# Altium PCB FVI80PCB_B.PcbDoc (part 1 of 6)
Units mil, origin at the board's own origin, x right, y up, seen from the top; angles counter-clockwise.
Board outline 3540 x 3115 mil, 12 copper layers (Top Layer, Int1(GND), Int2(Signal), Int3(GND), Int4(Signal), Int5 (GND&PW), Int6 (GND&PW), Int7(Signal), Int8(GND), Int9(Signal), Int10(GND), Bottom Layer), stack 77.136 mil thick; 488 components, 321 nets, 1809 pads, 882 vias.
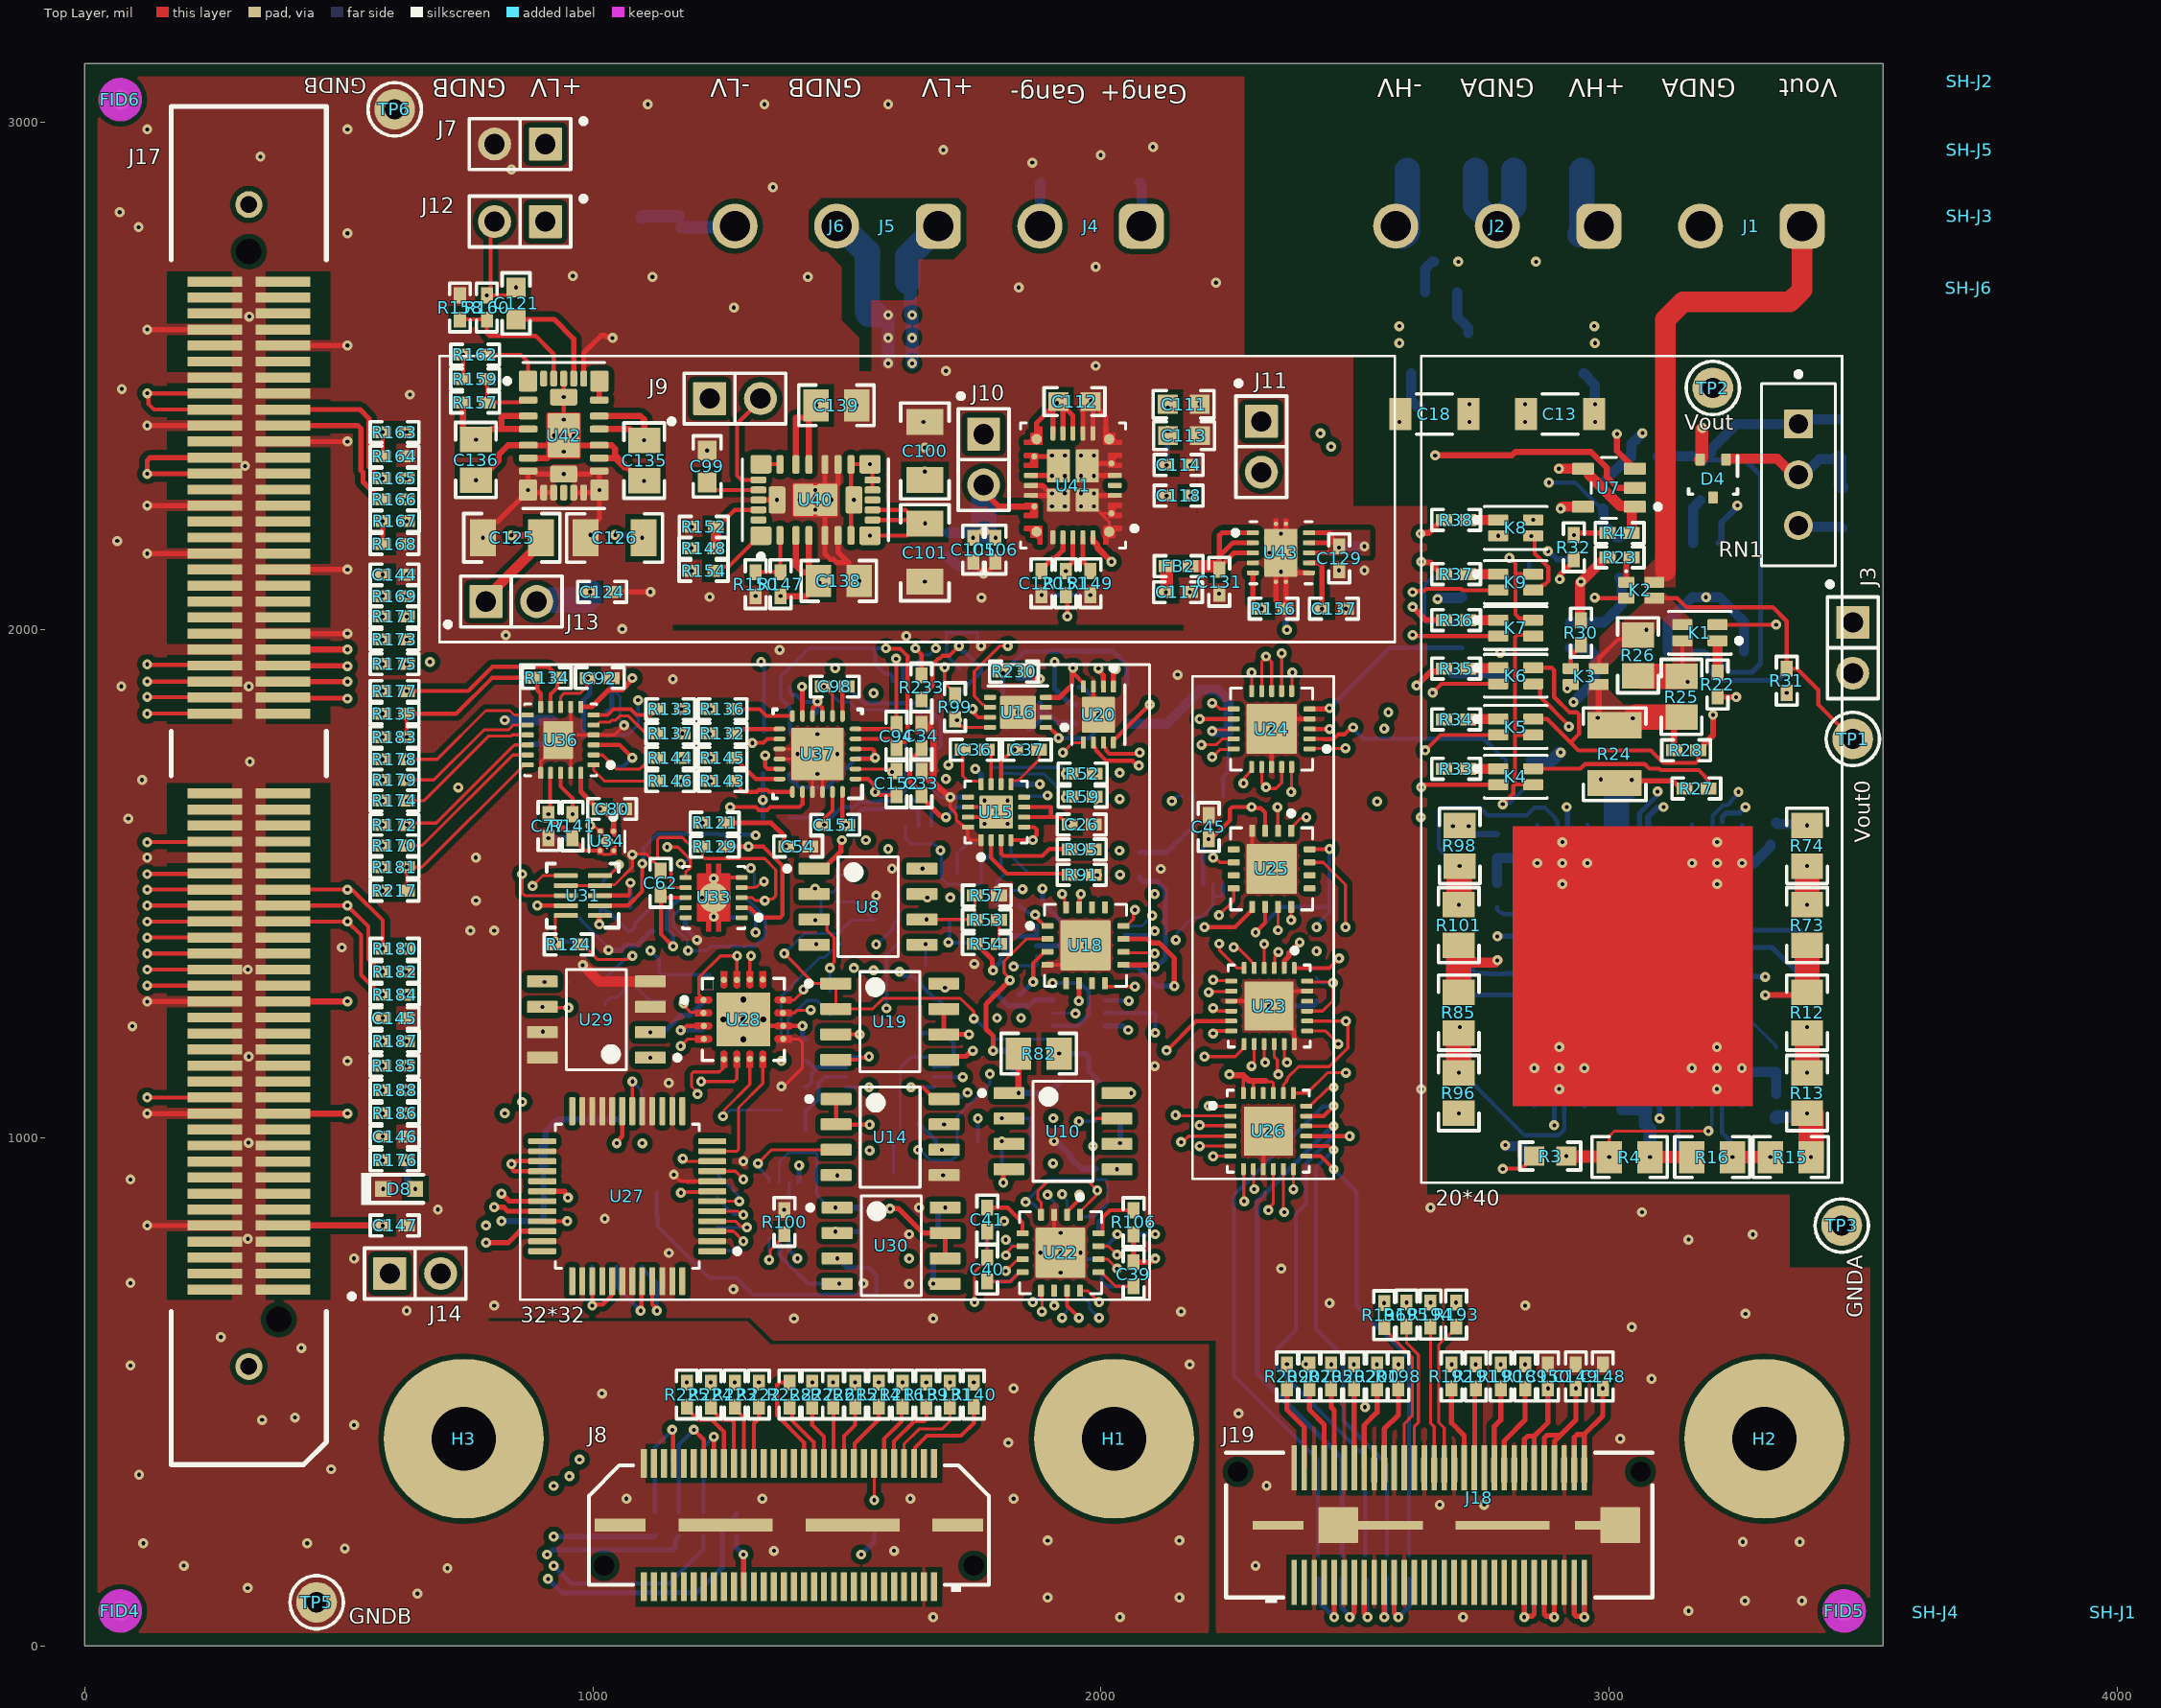
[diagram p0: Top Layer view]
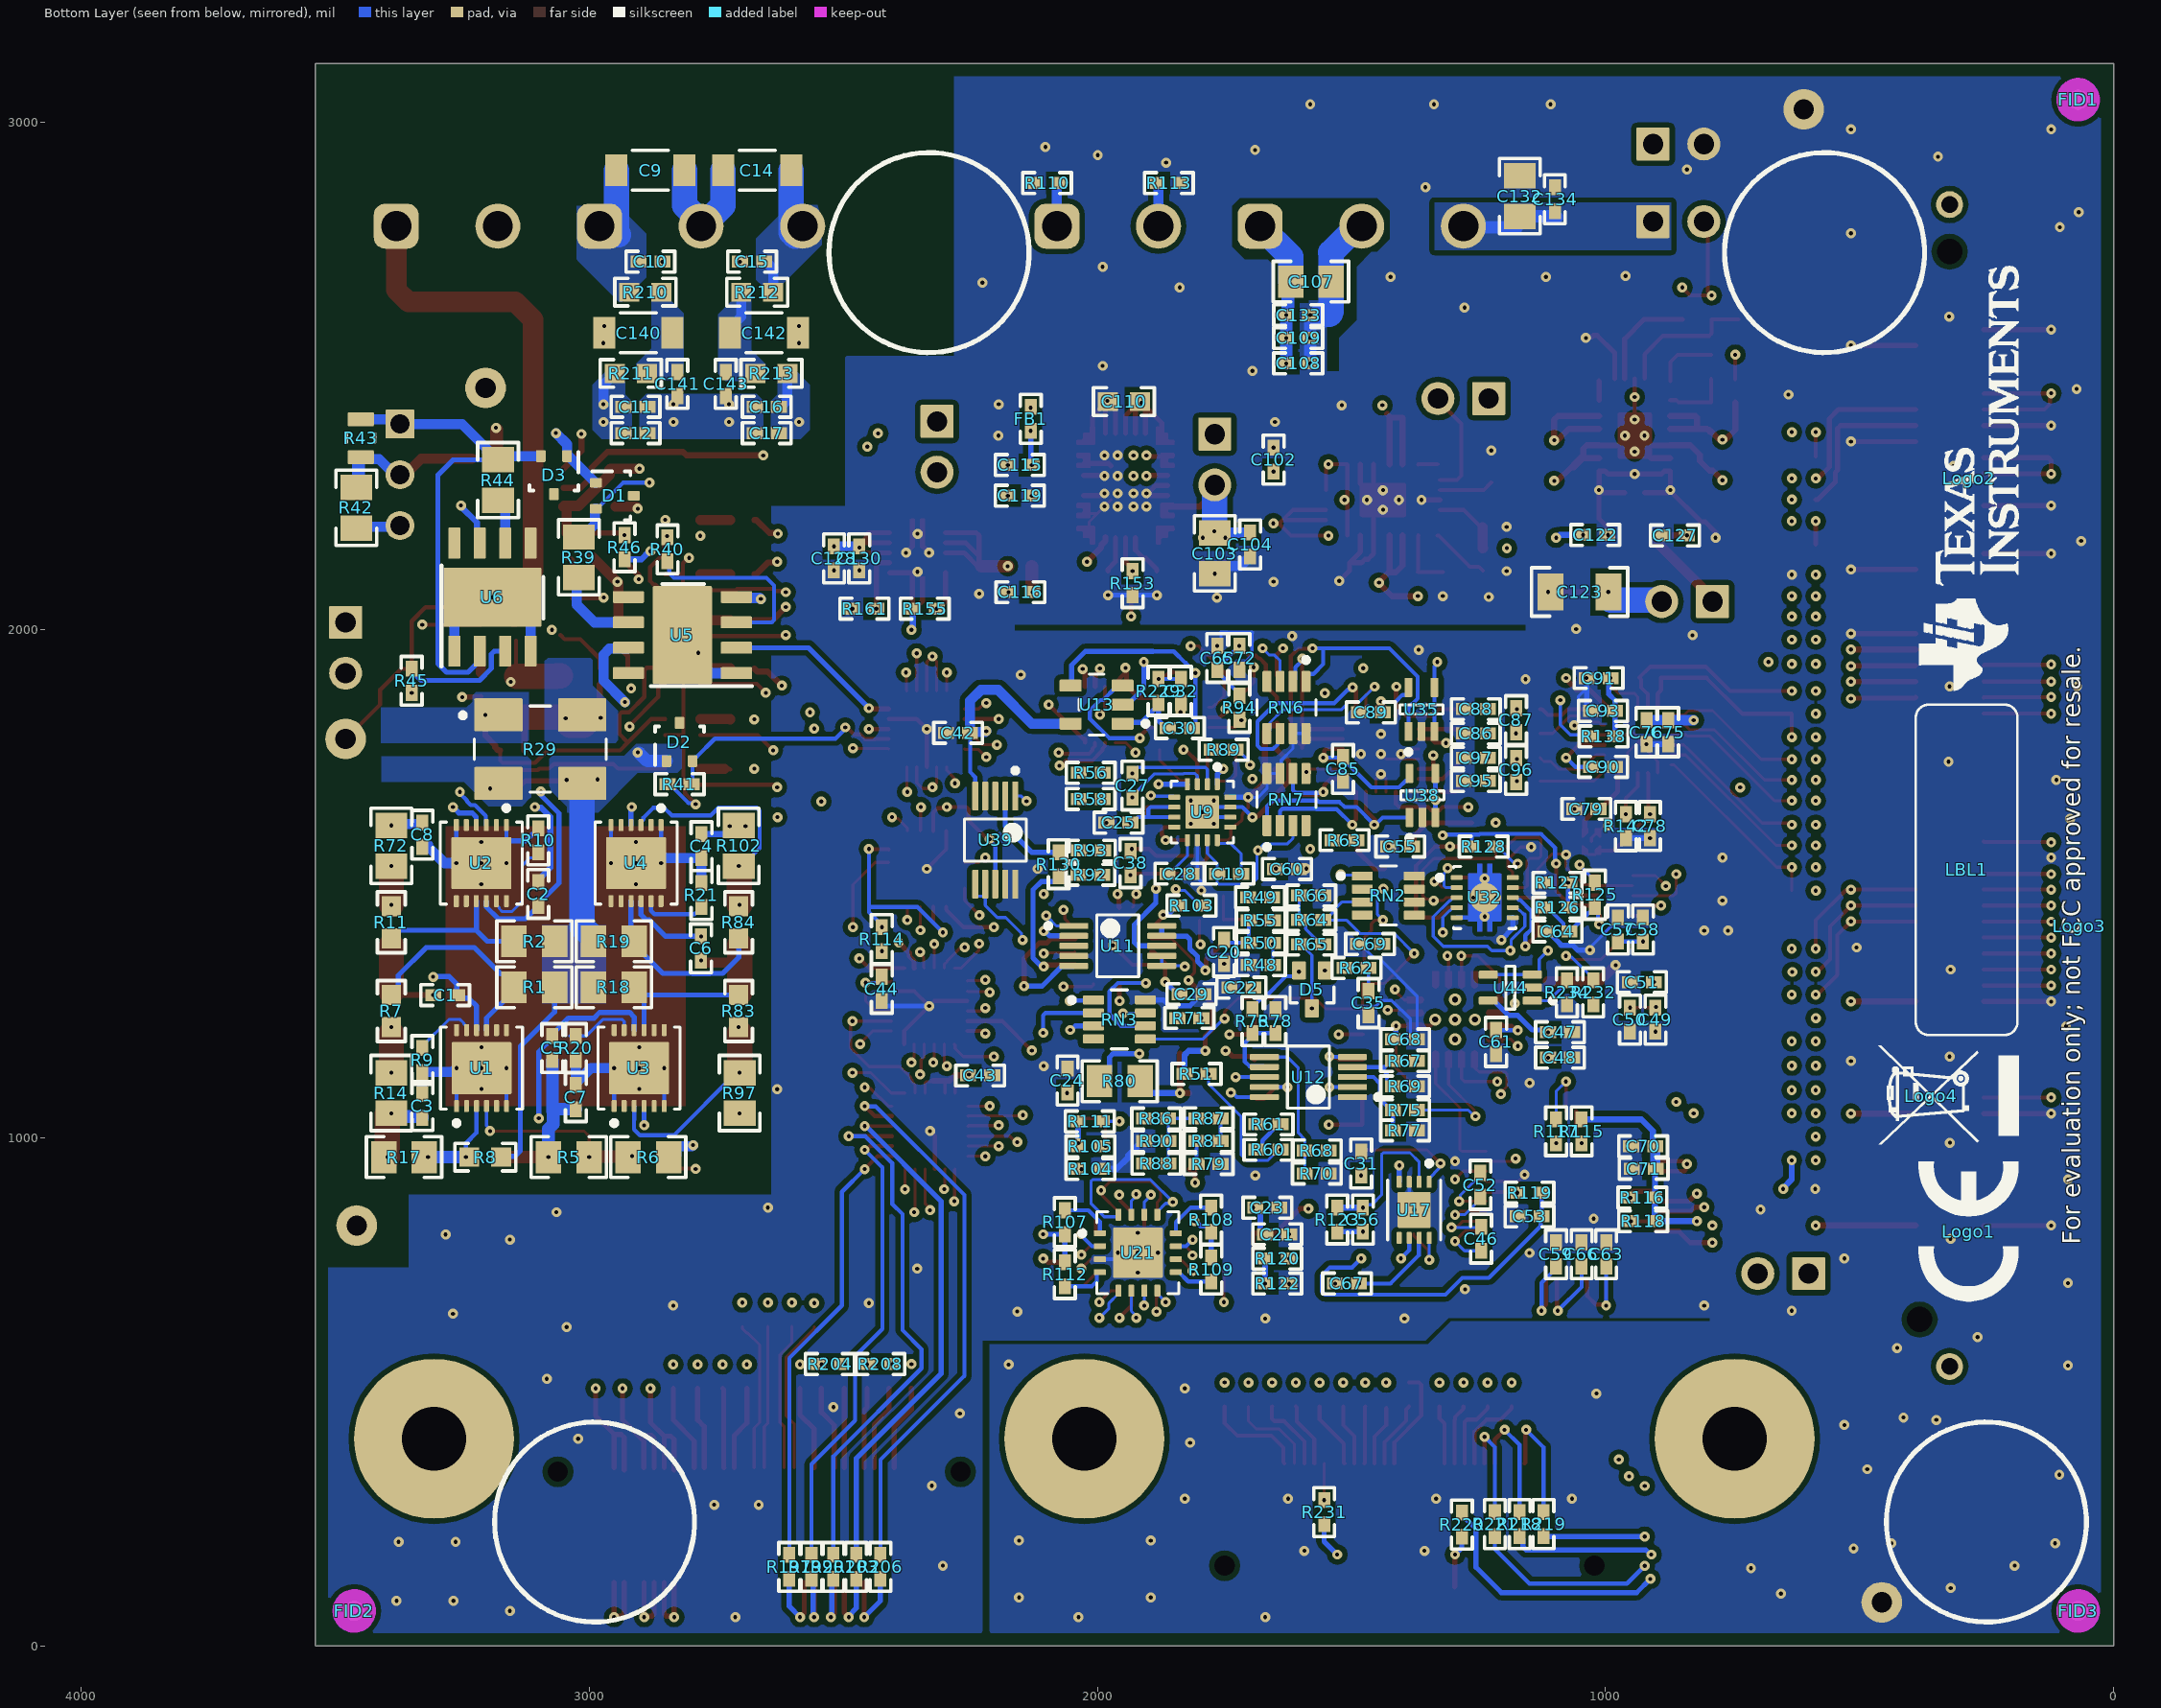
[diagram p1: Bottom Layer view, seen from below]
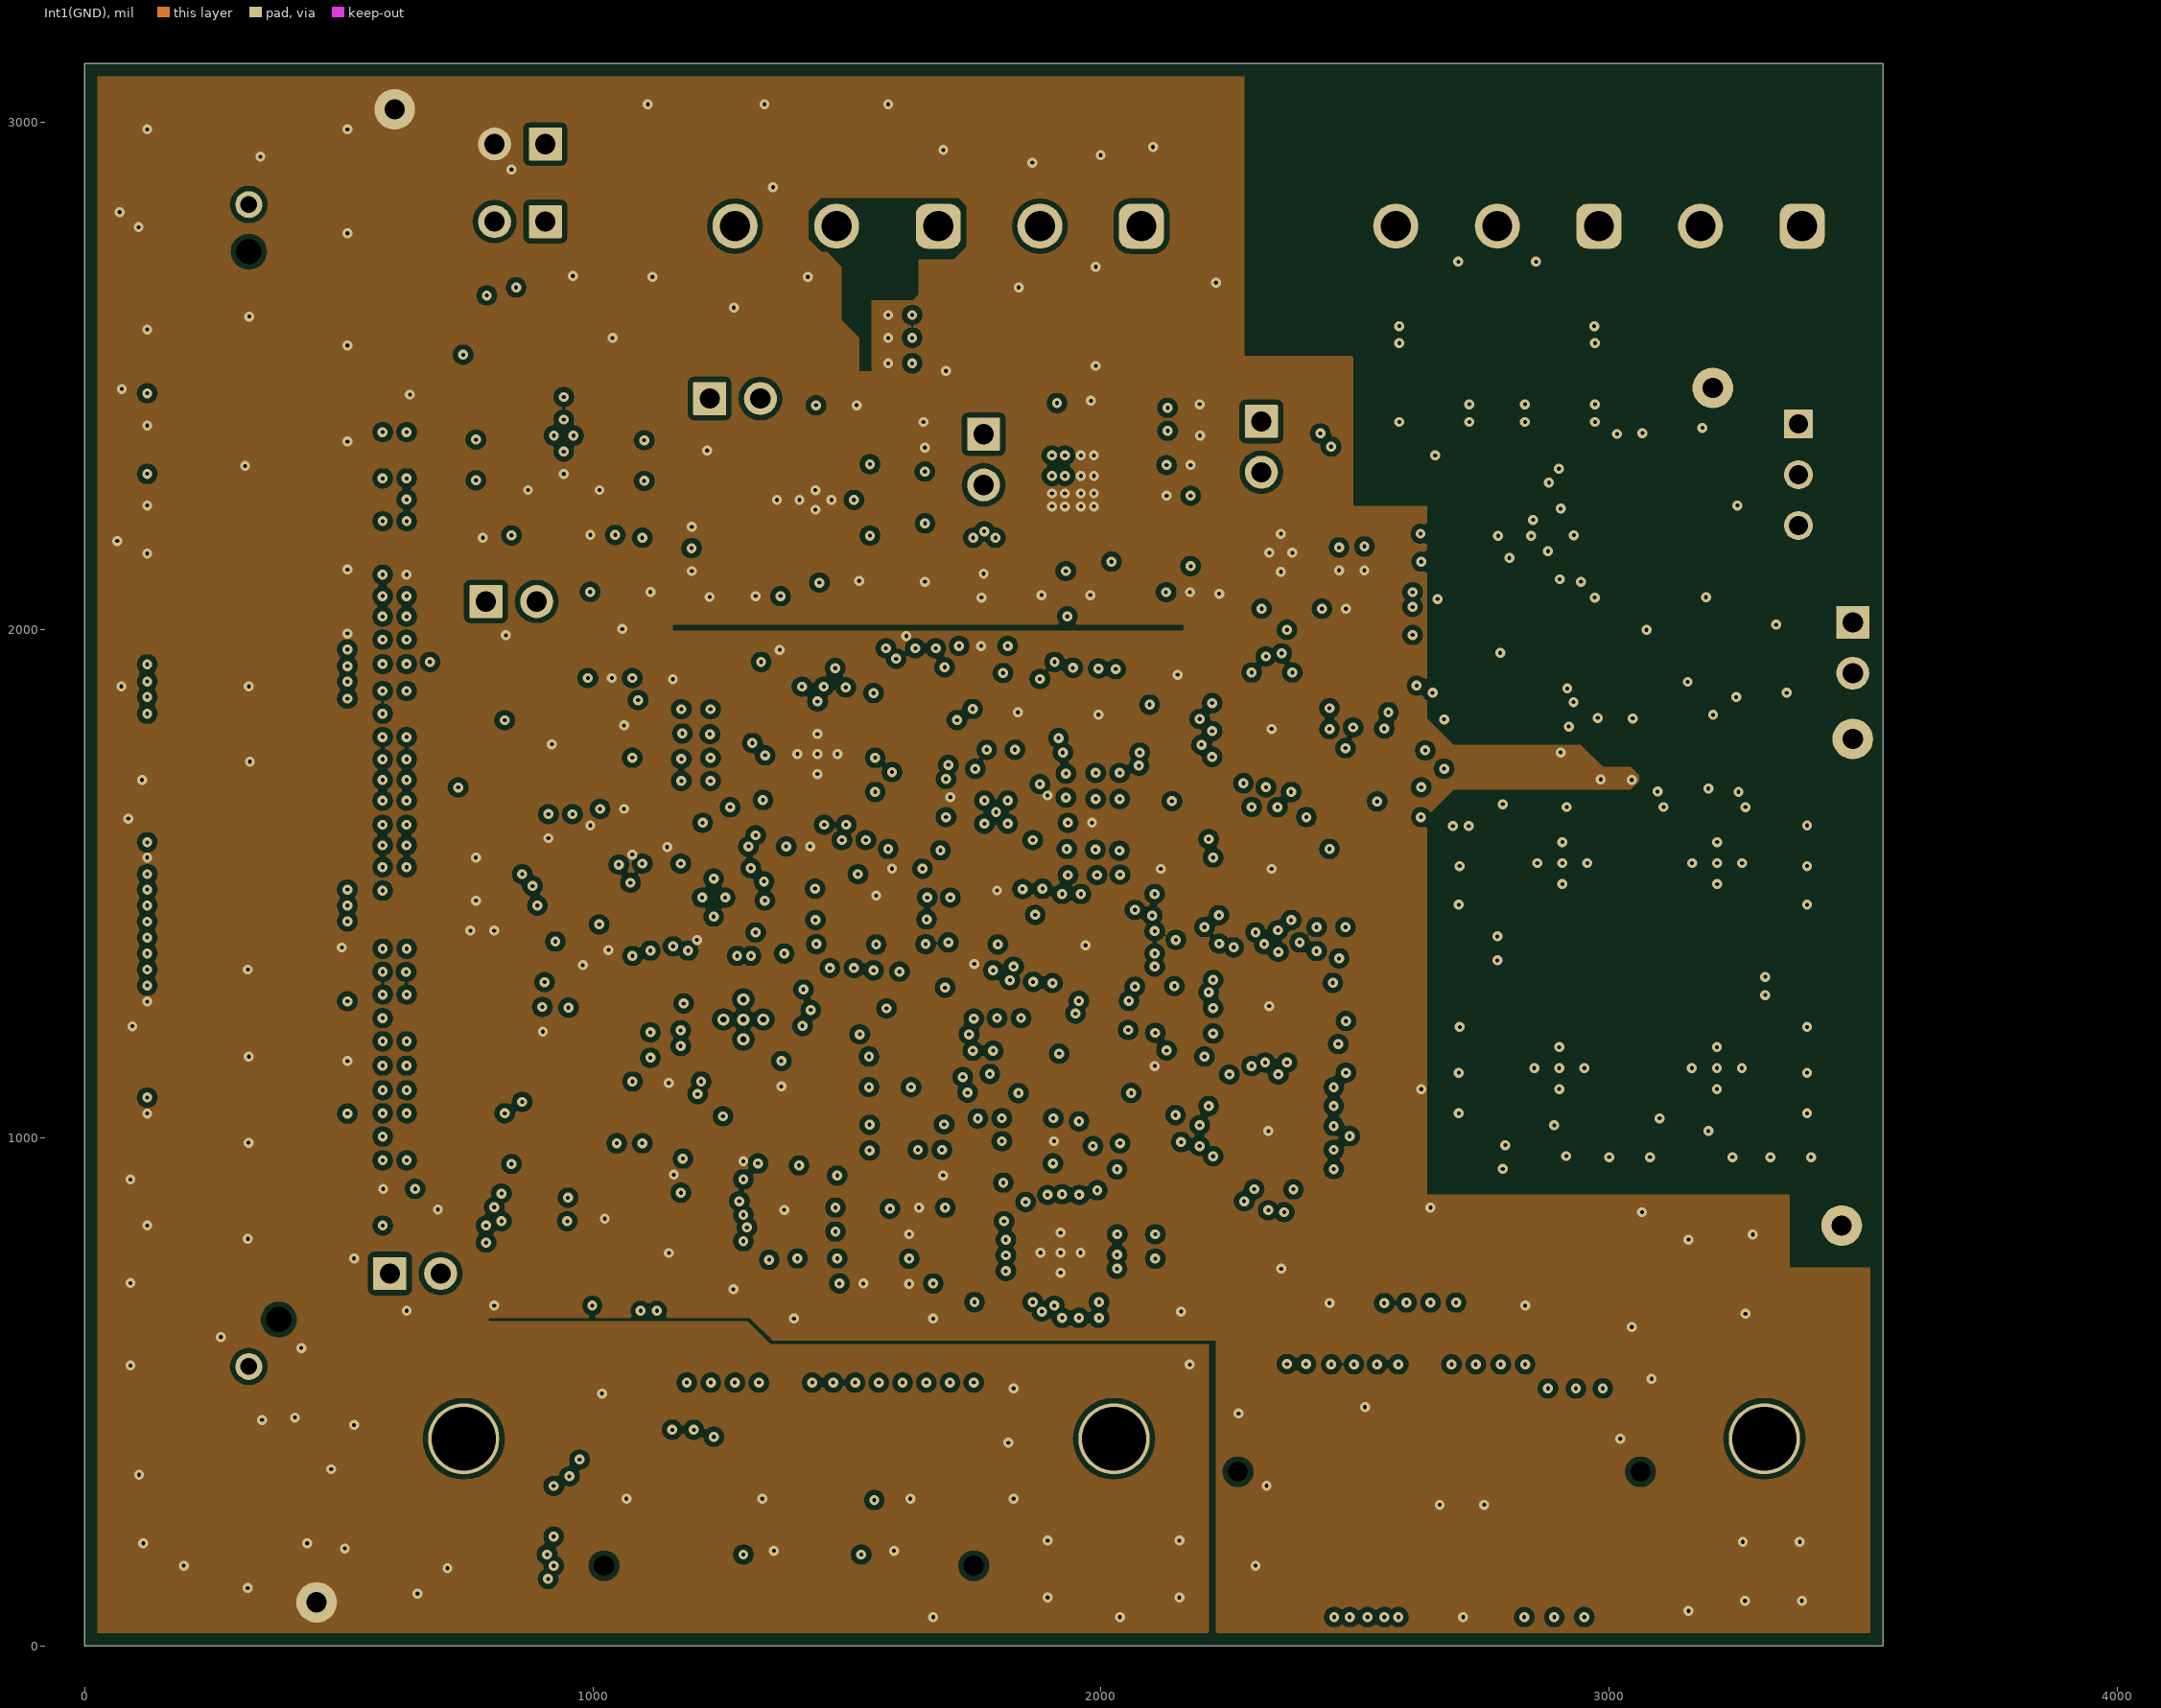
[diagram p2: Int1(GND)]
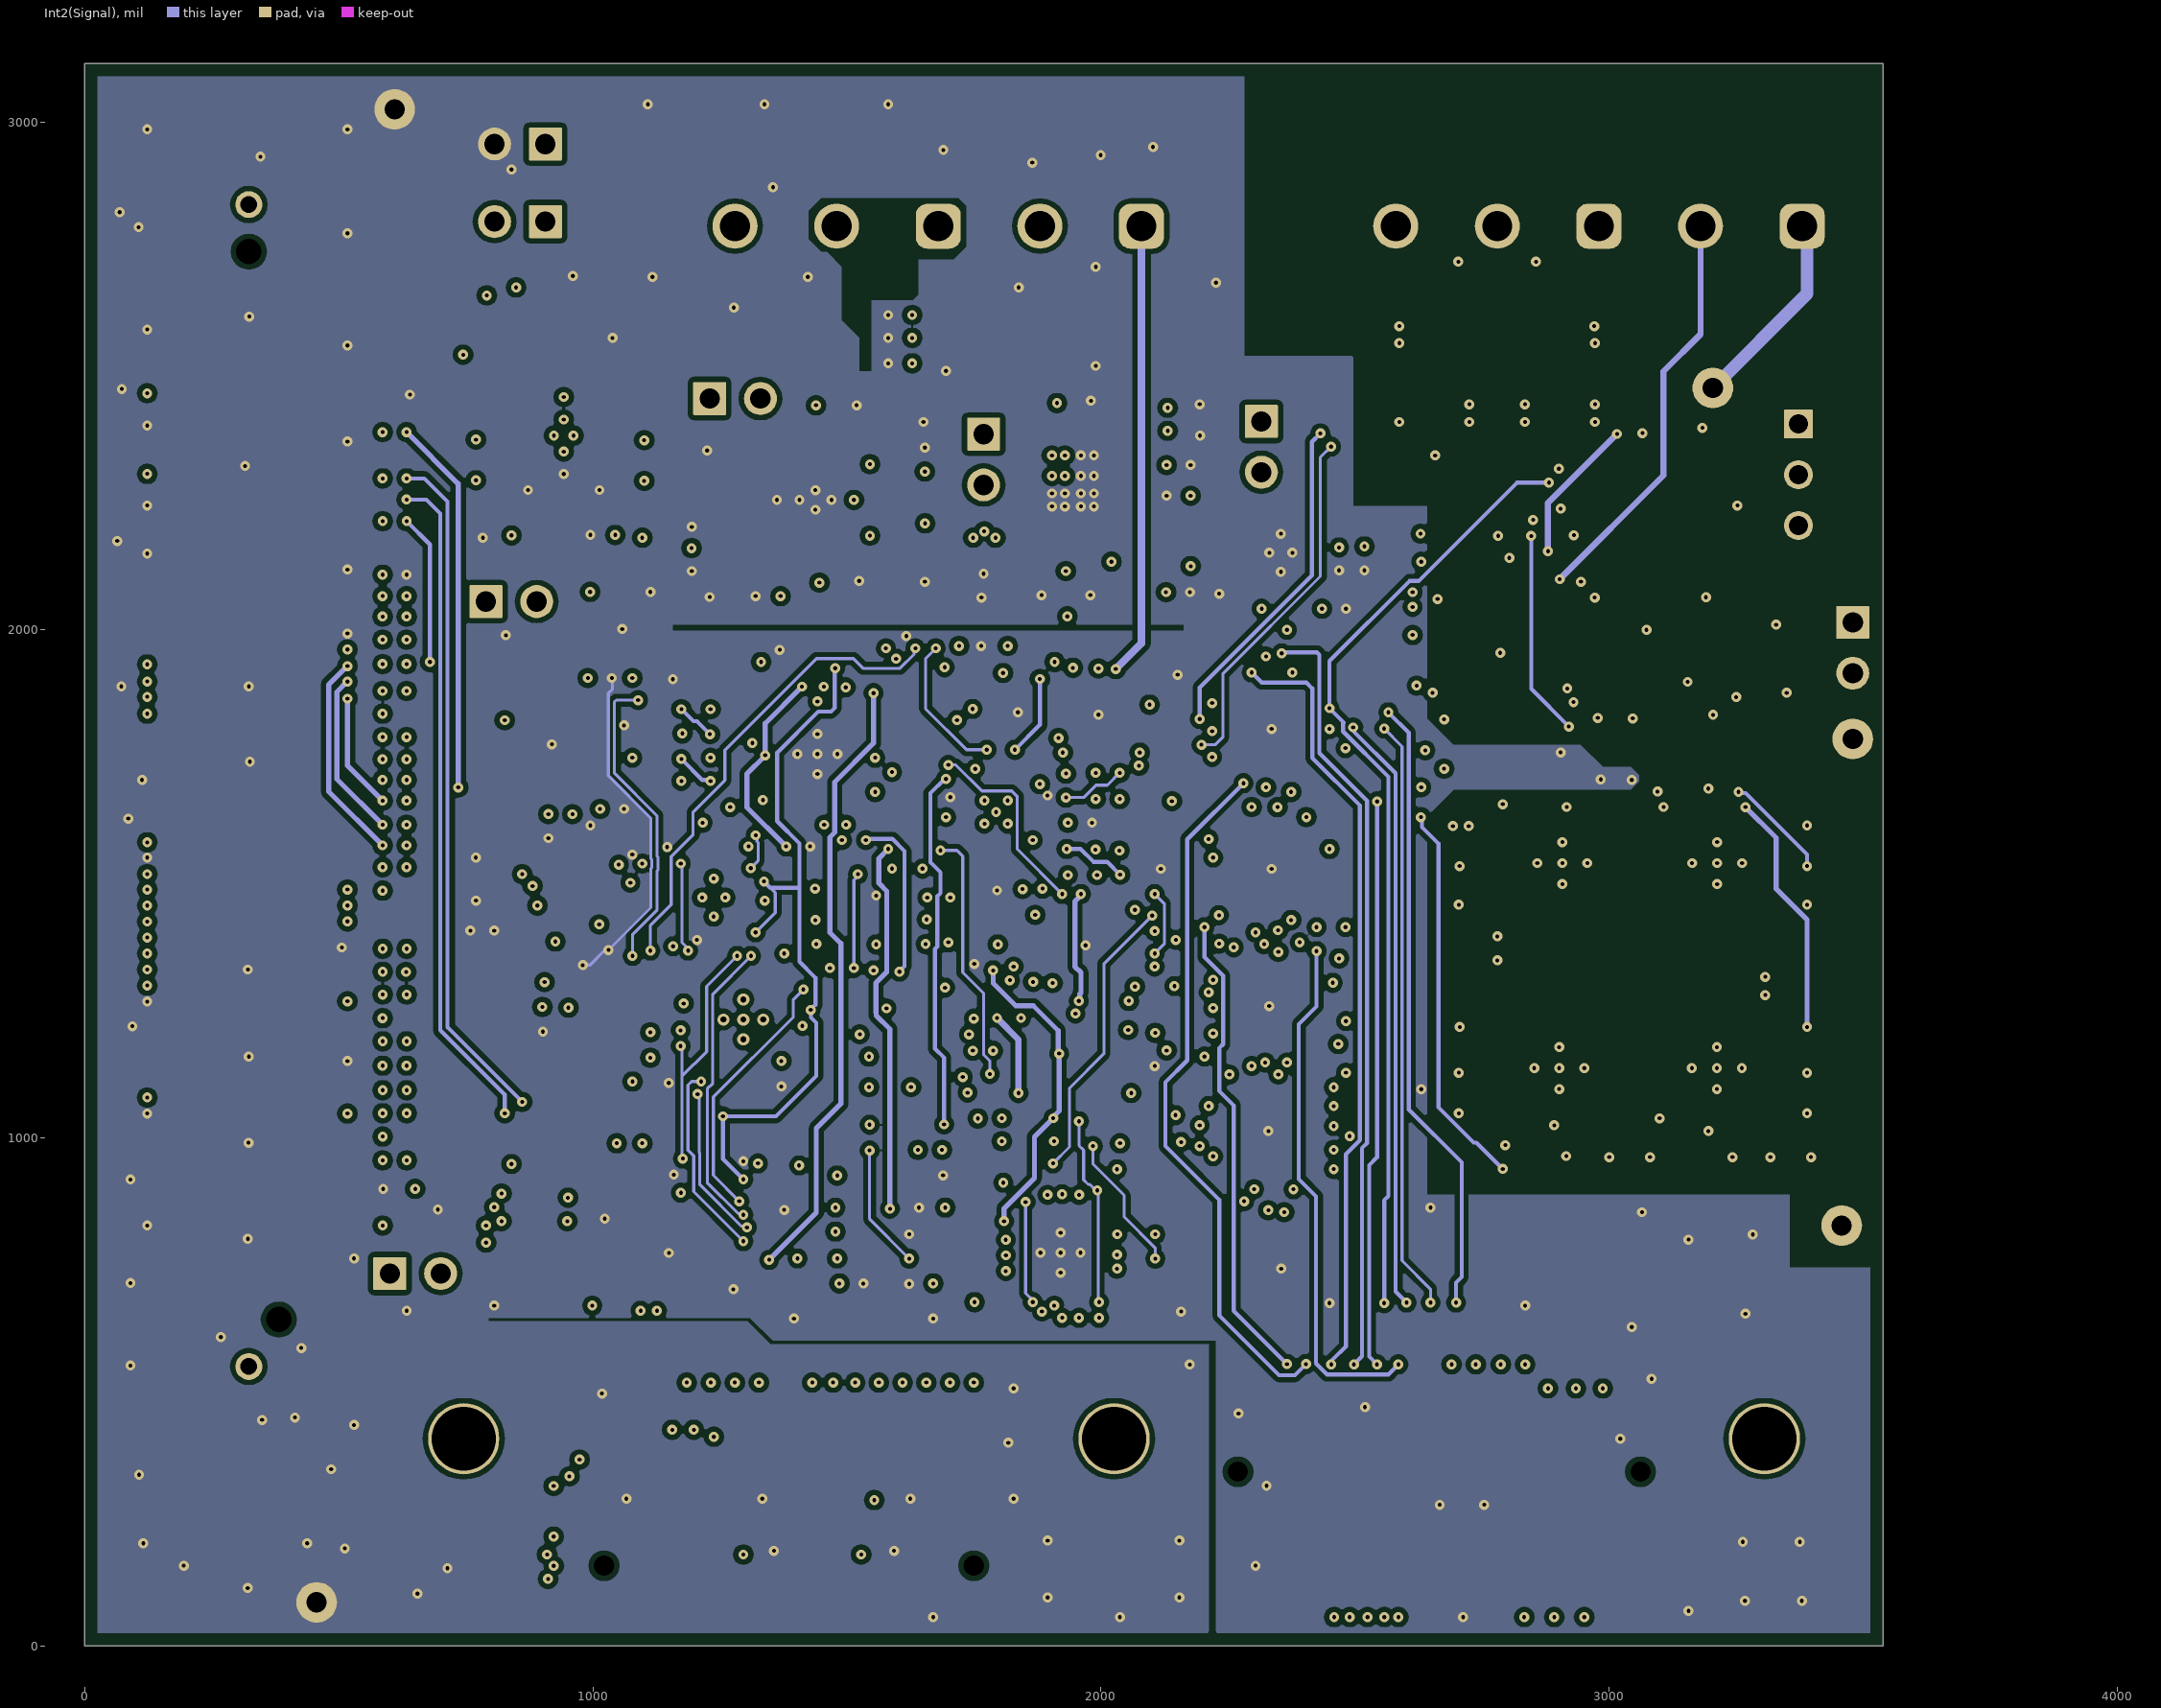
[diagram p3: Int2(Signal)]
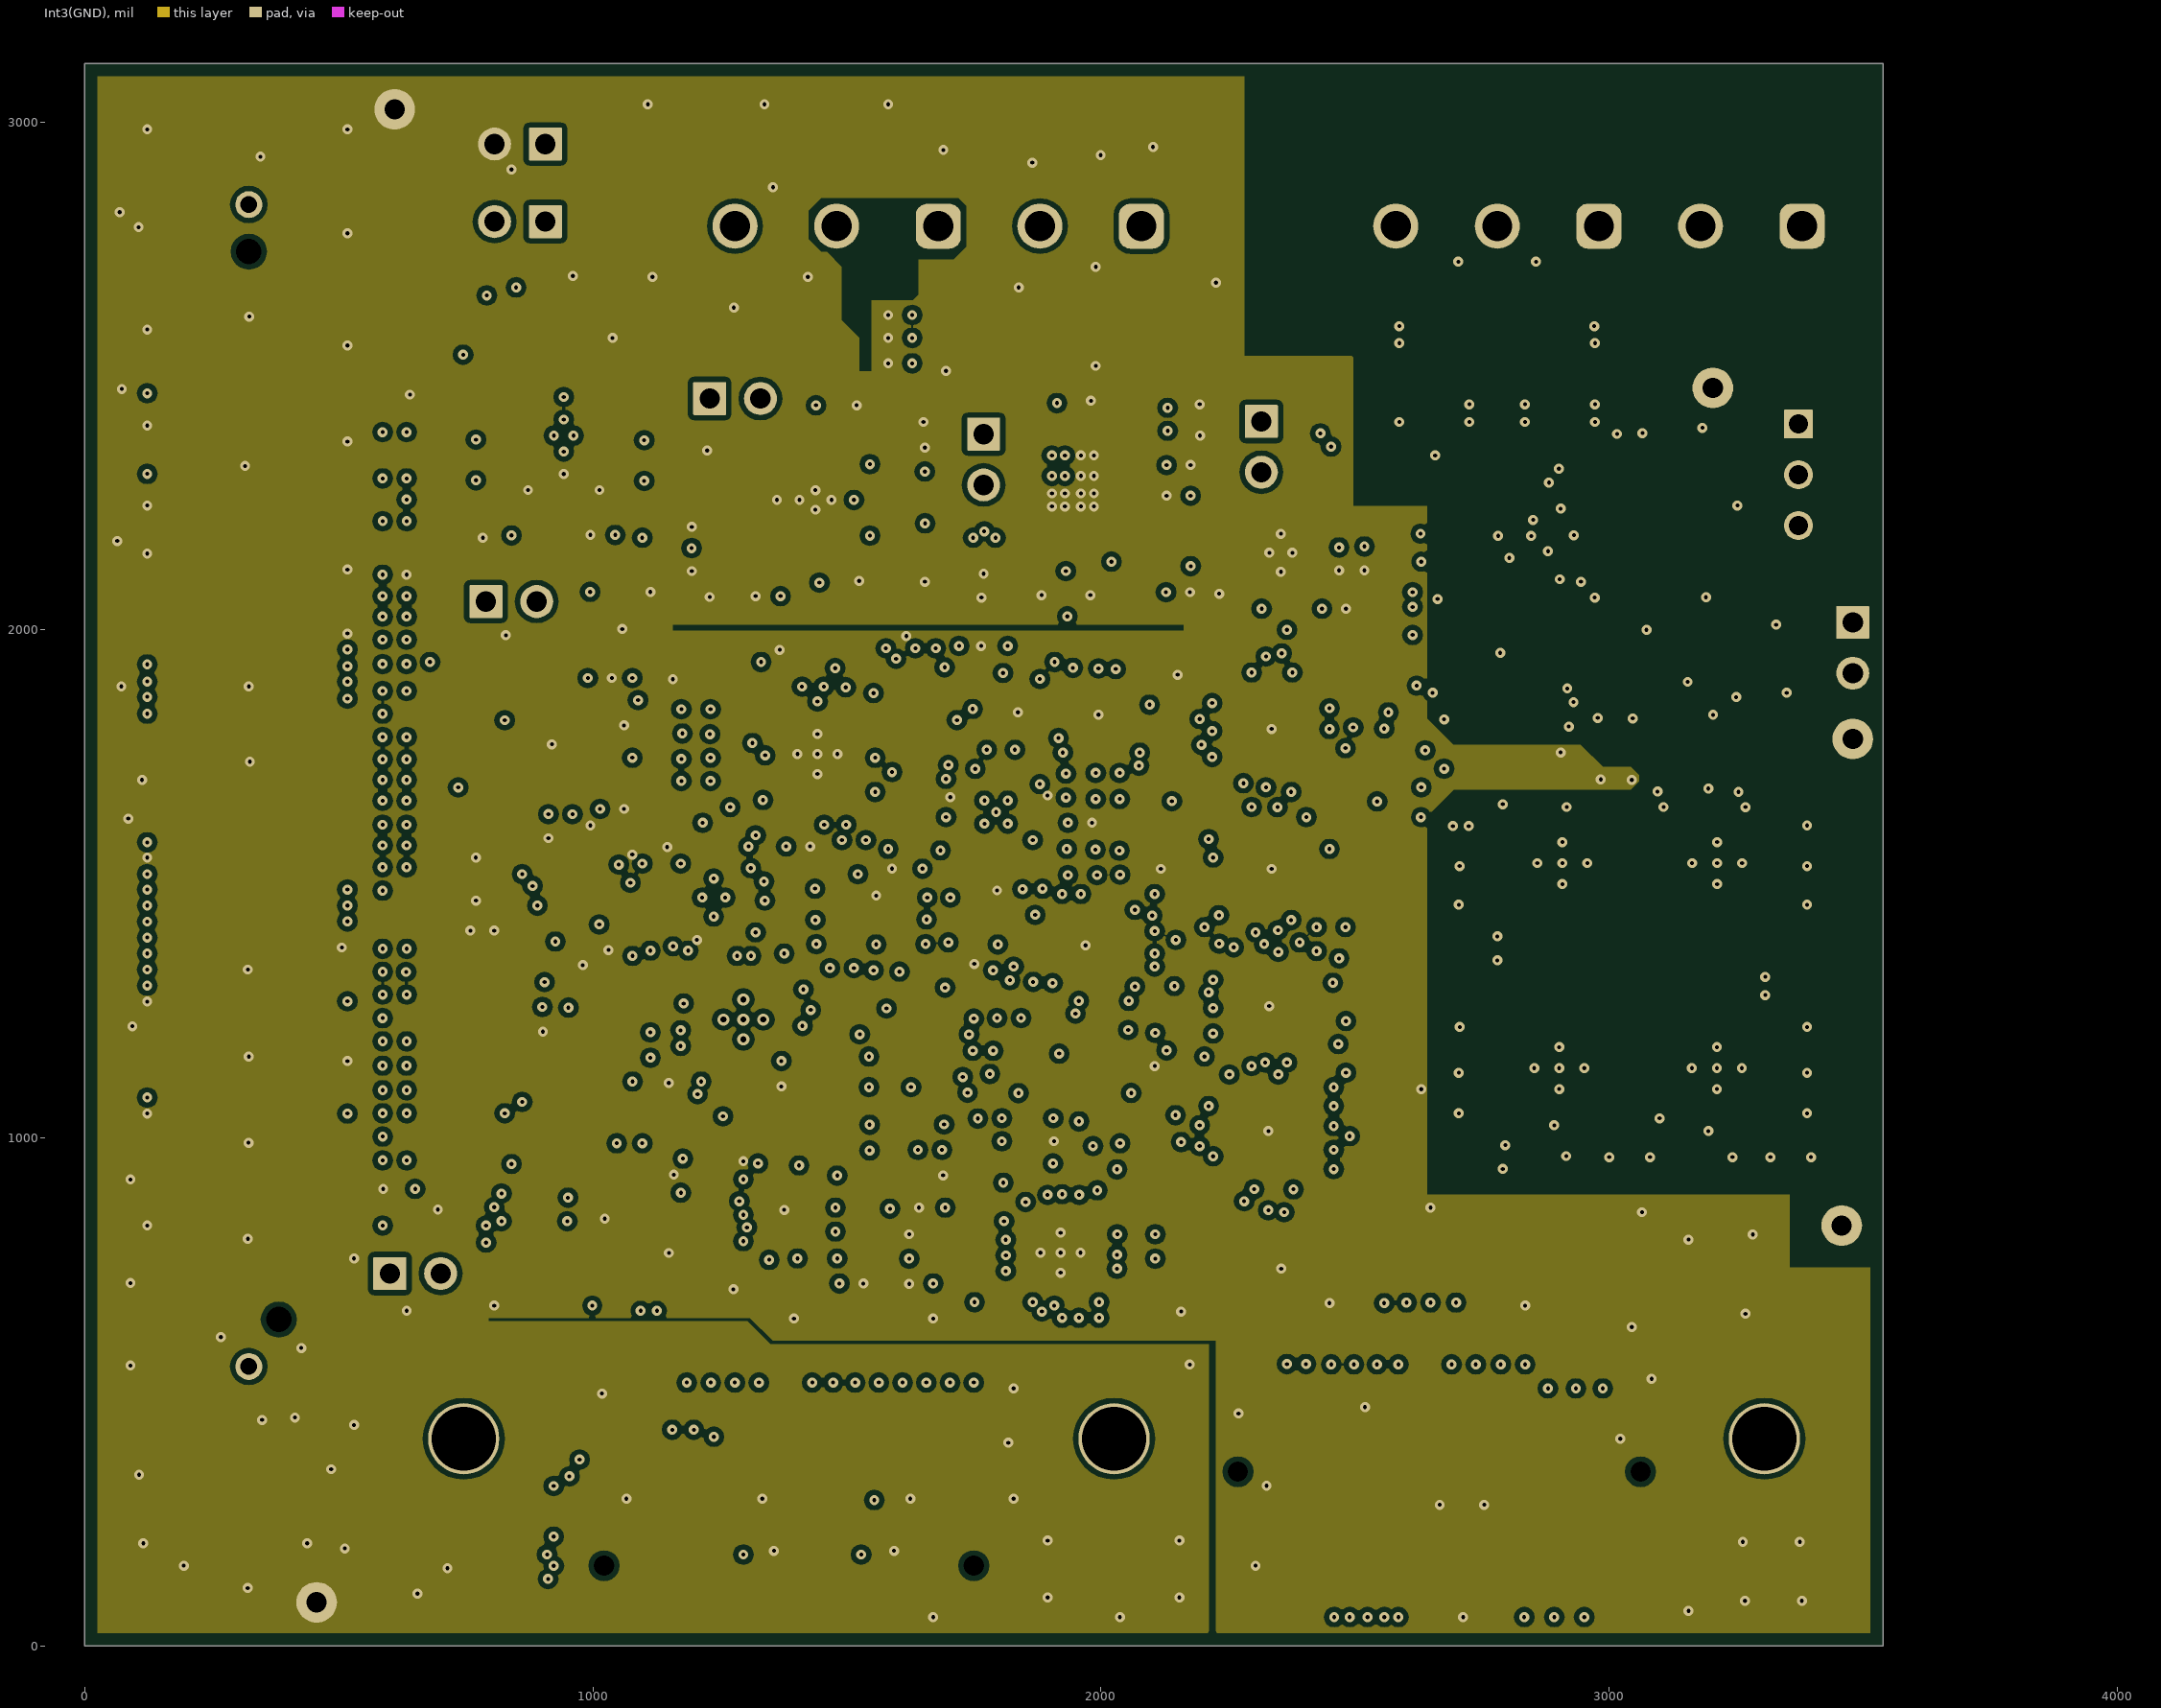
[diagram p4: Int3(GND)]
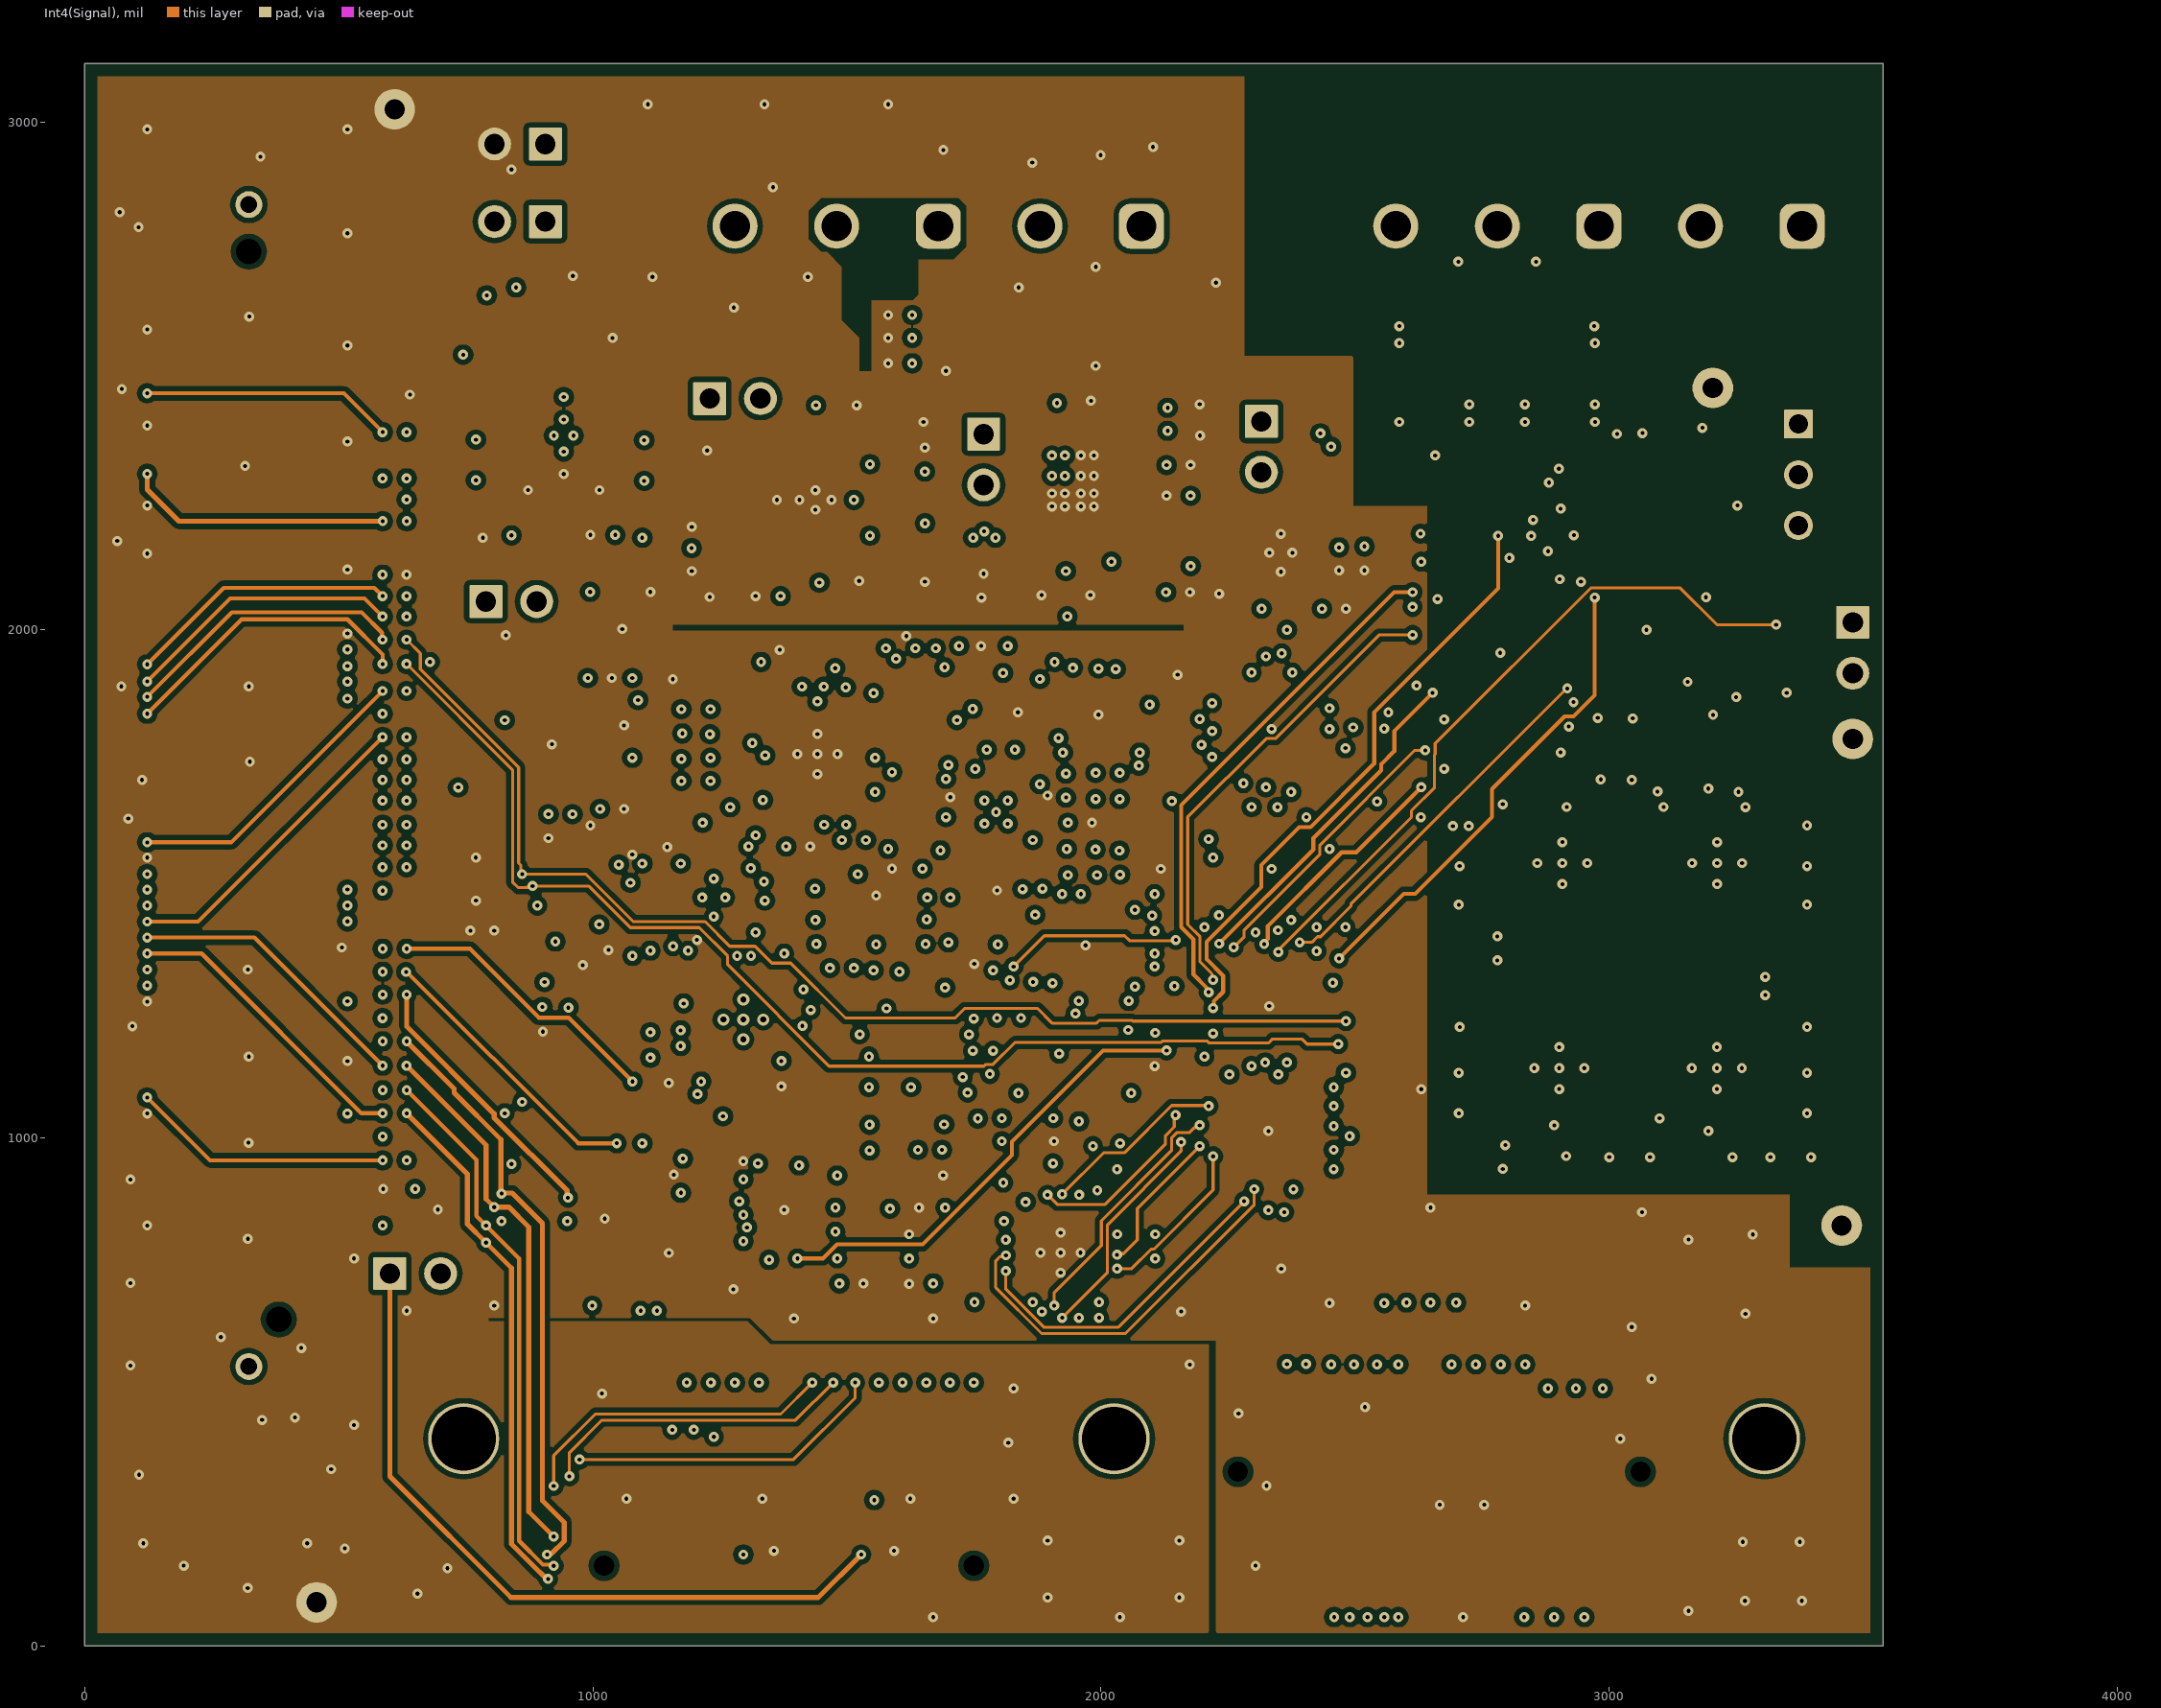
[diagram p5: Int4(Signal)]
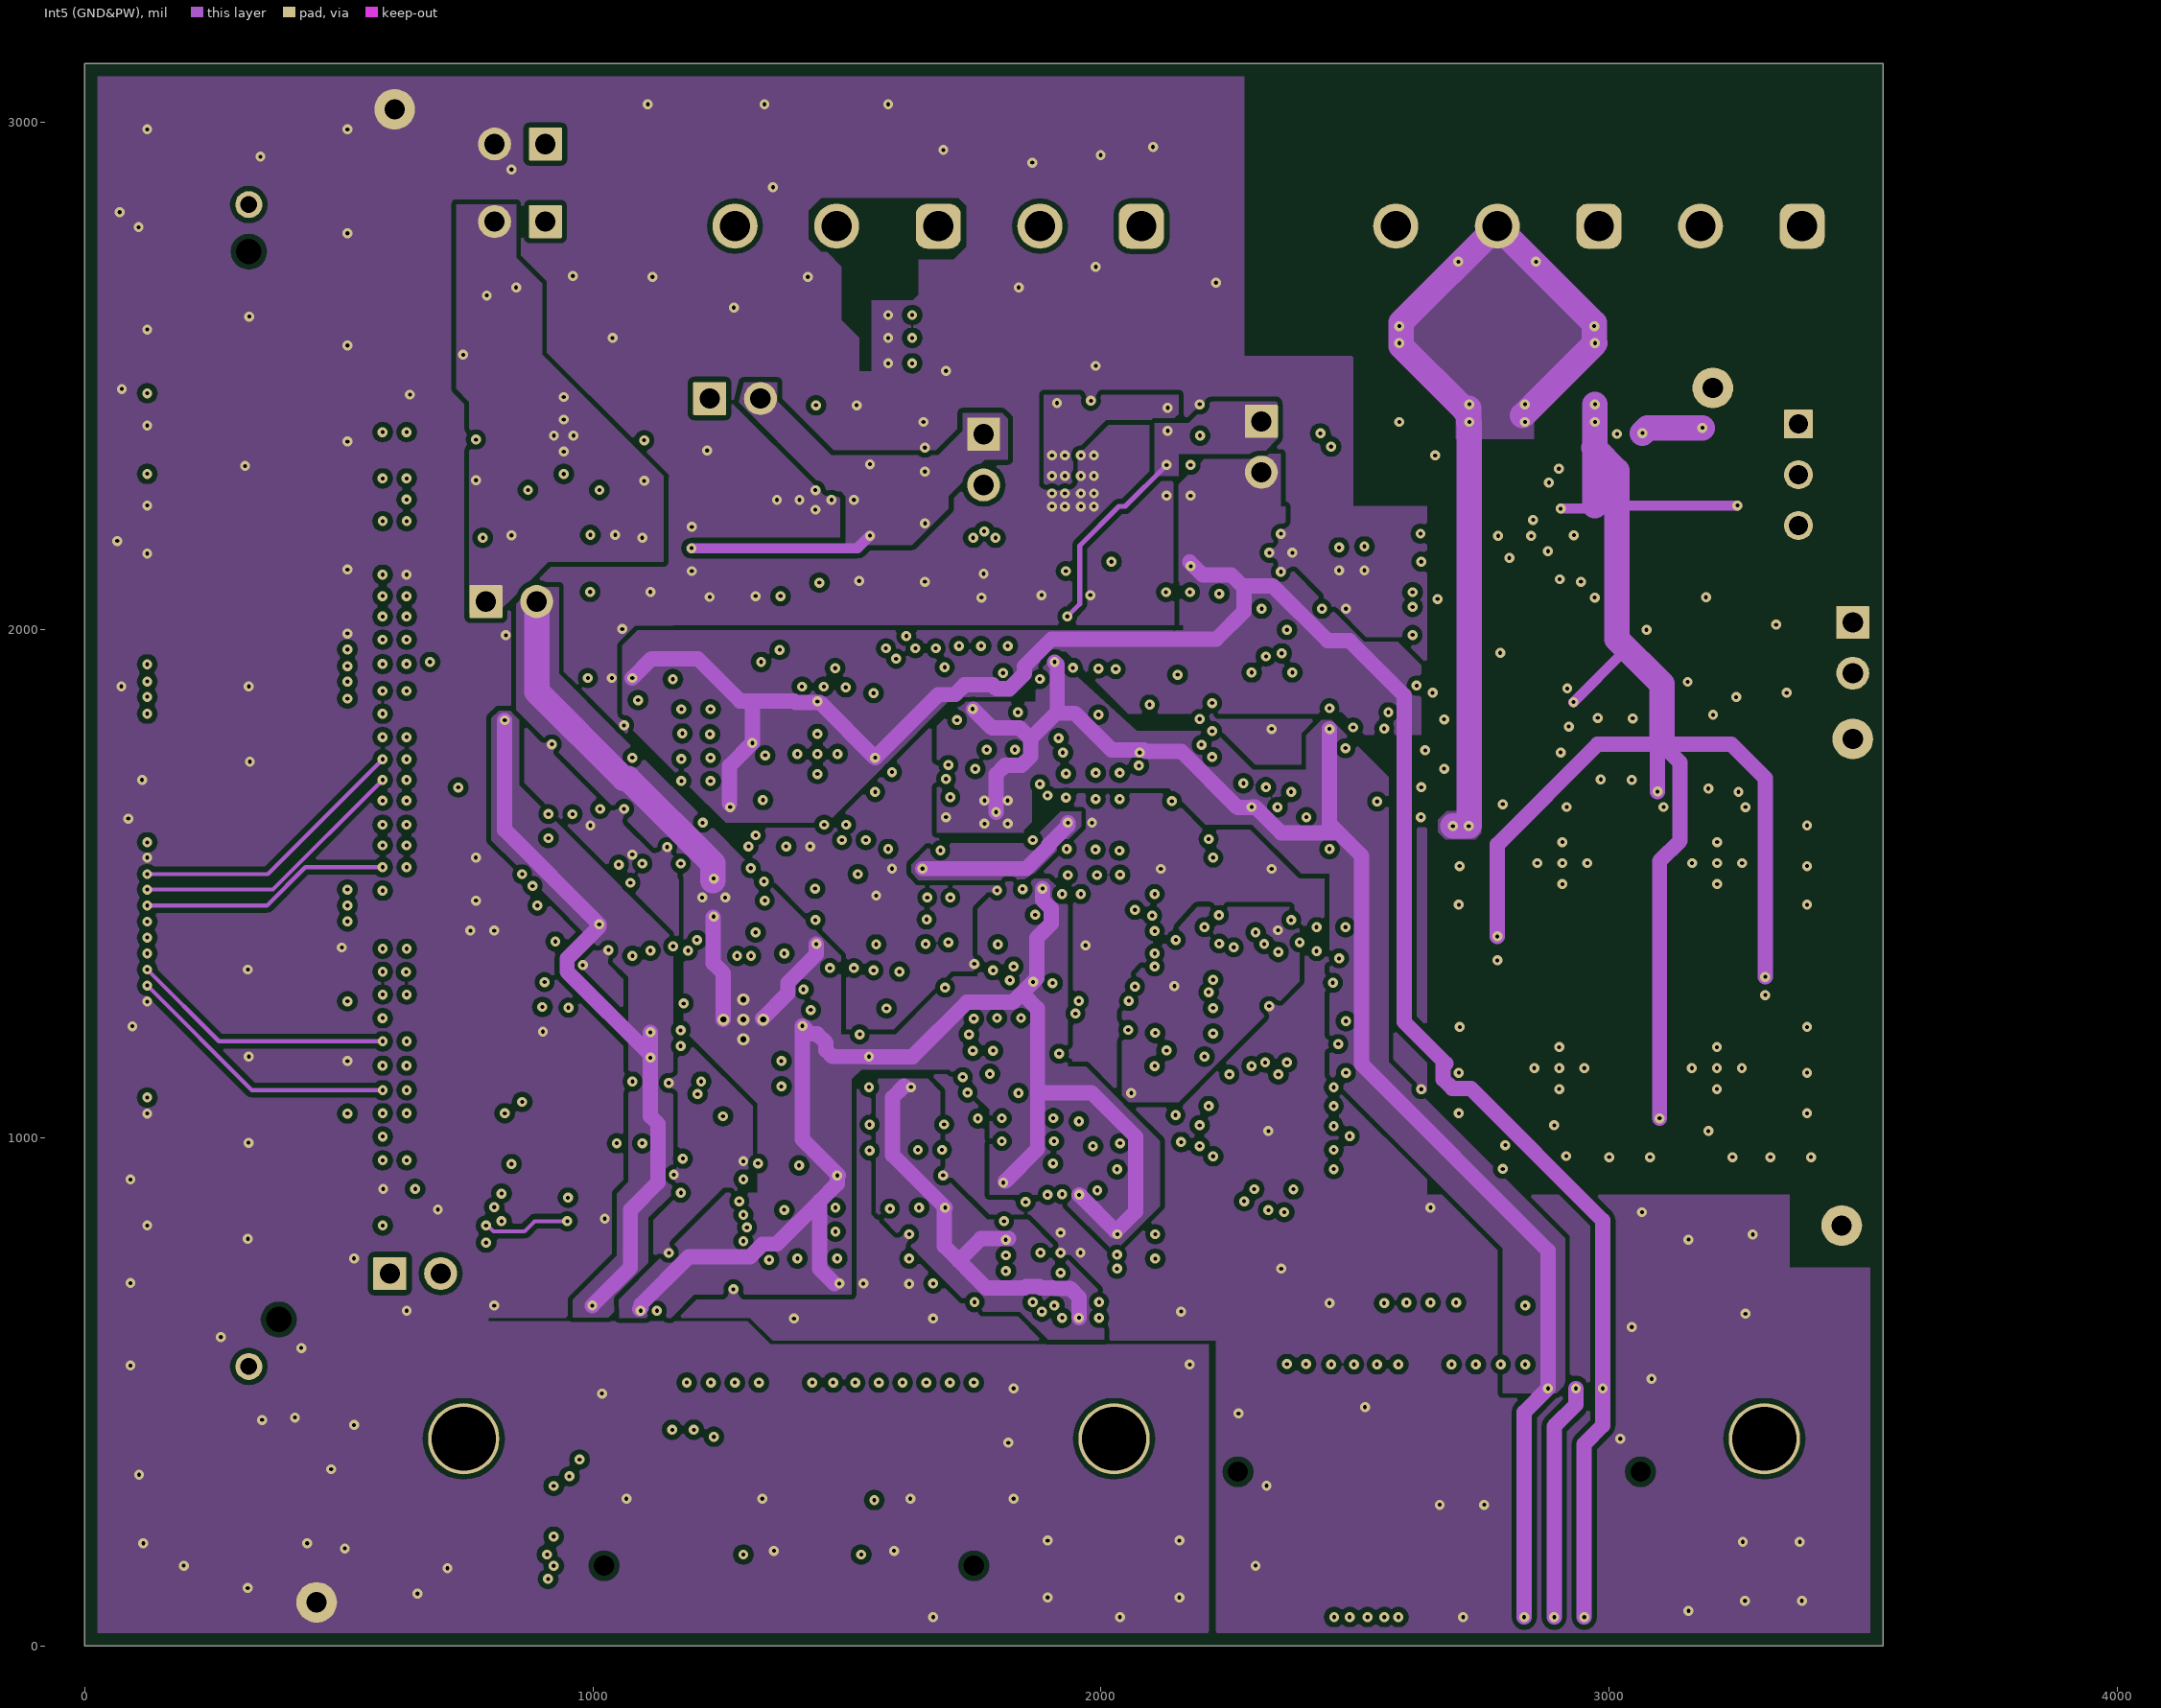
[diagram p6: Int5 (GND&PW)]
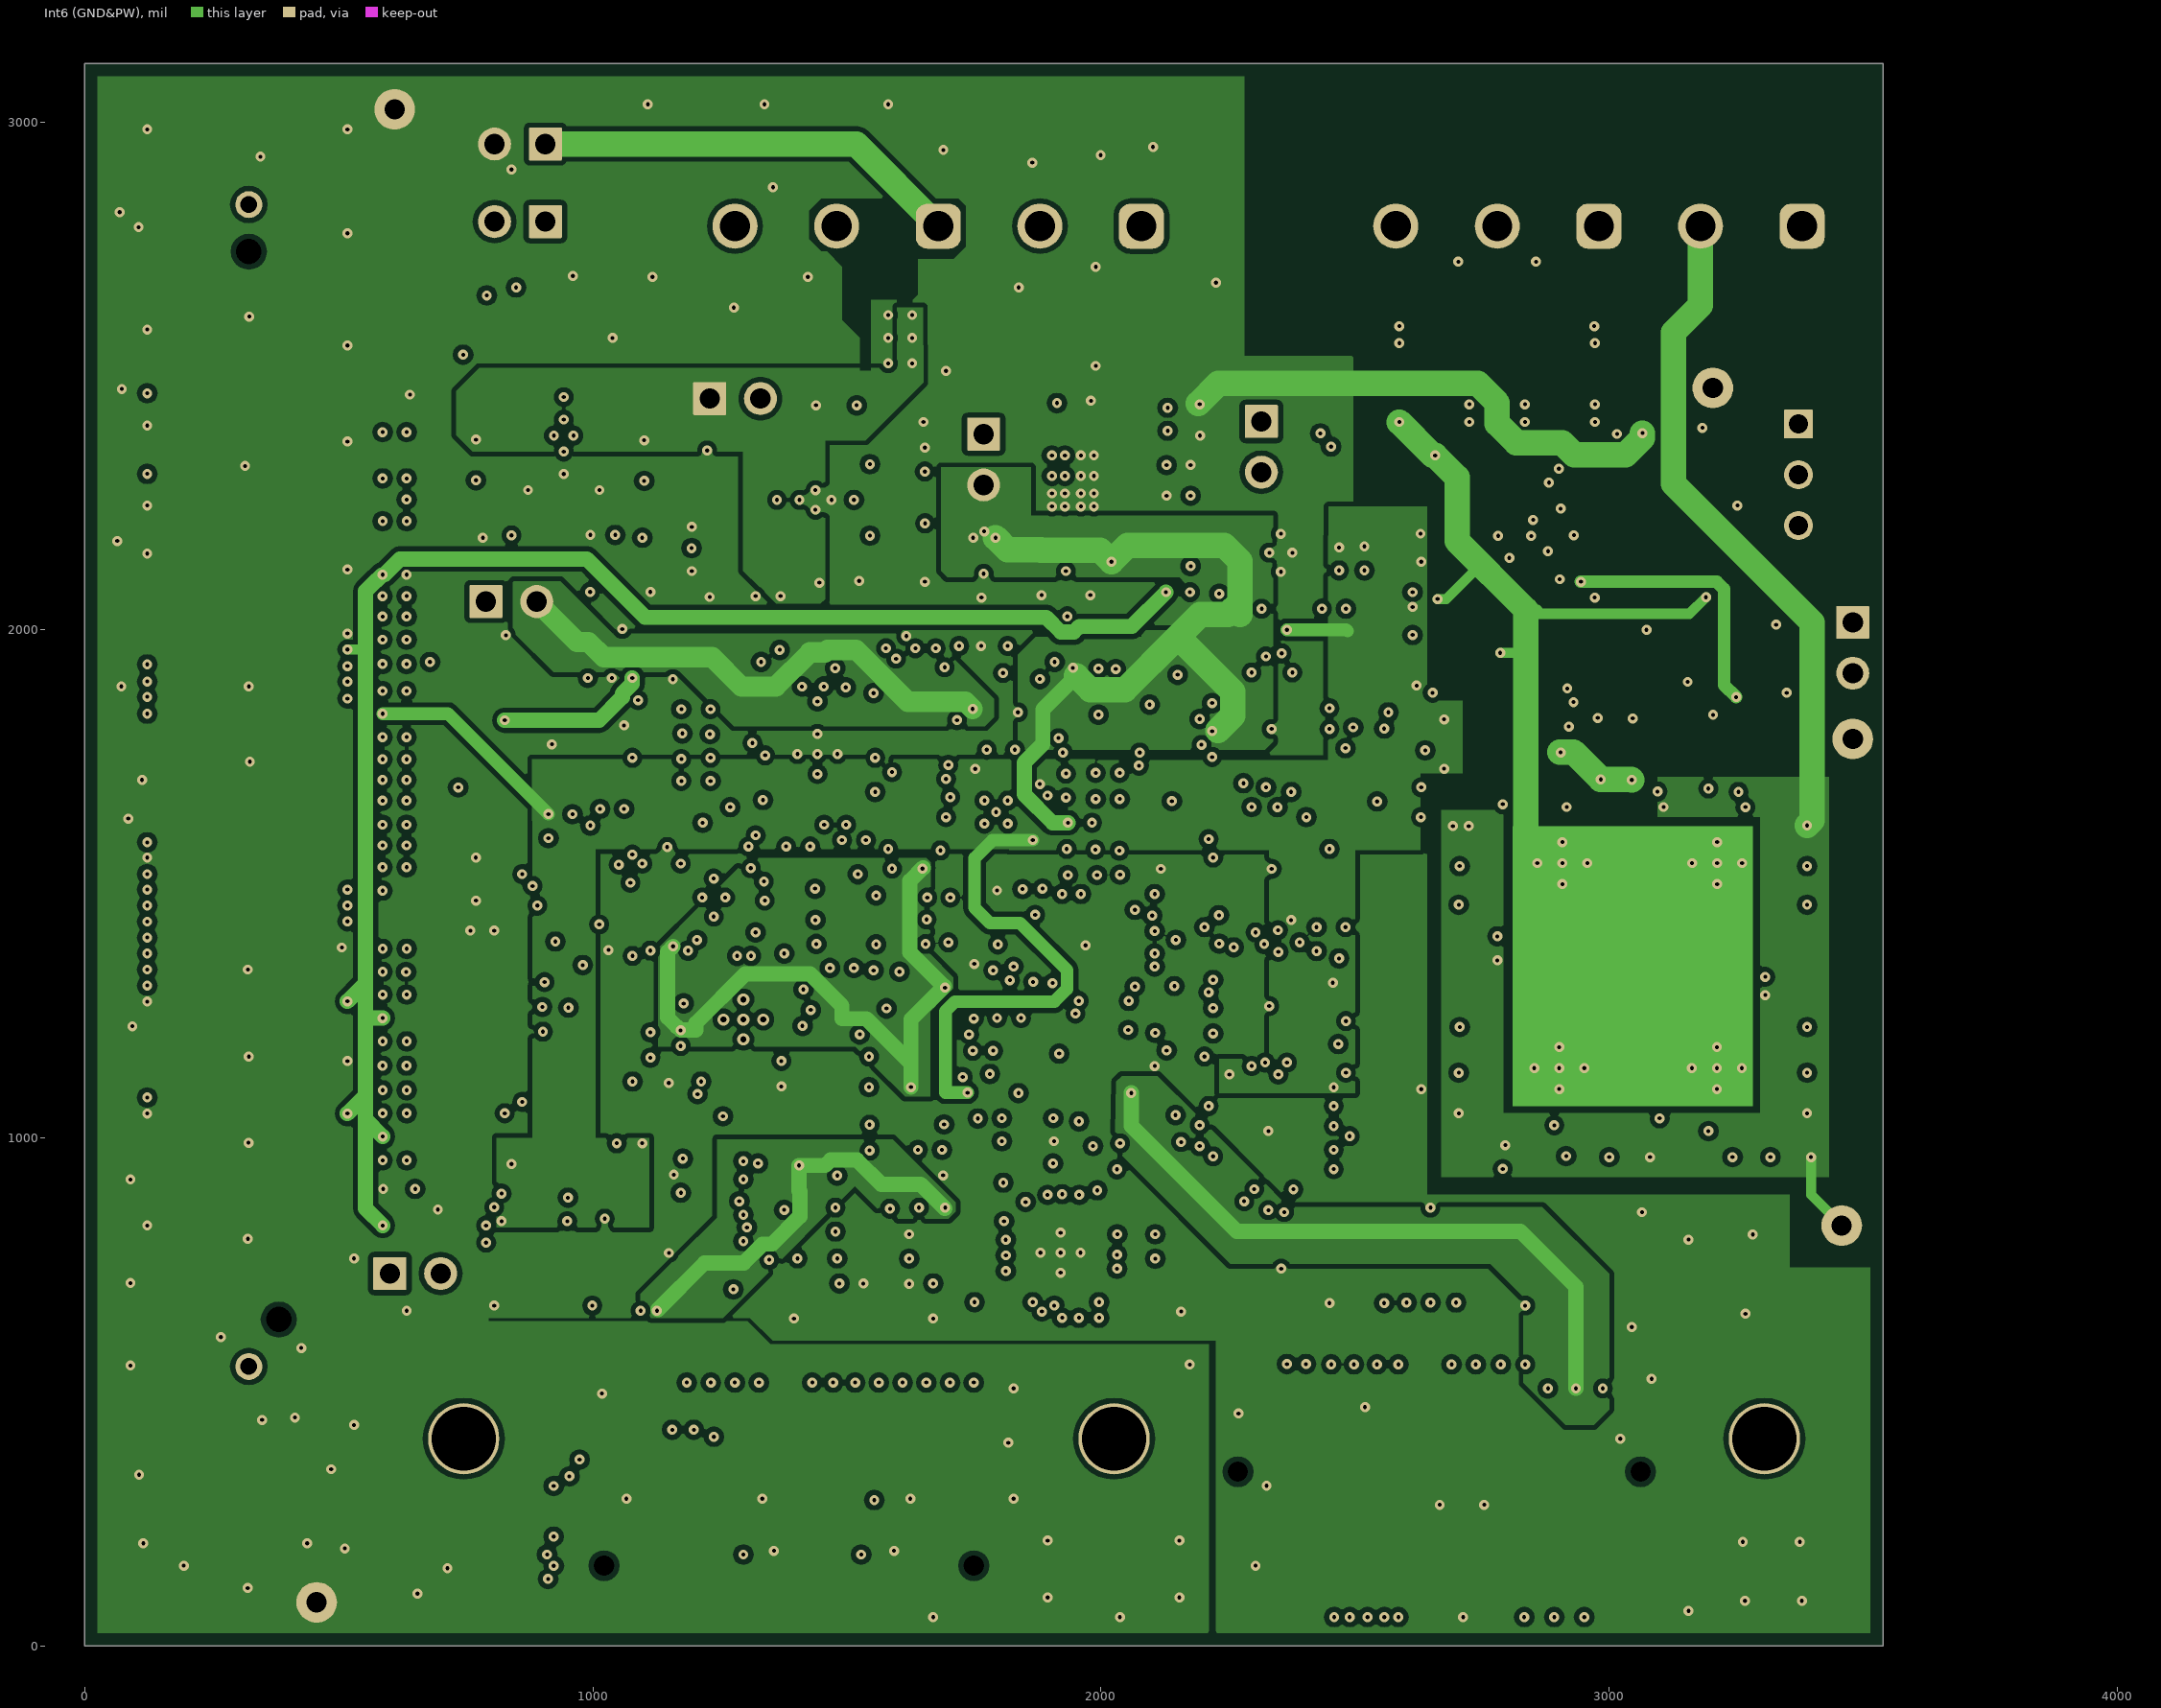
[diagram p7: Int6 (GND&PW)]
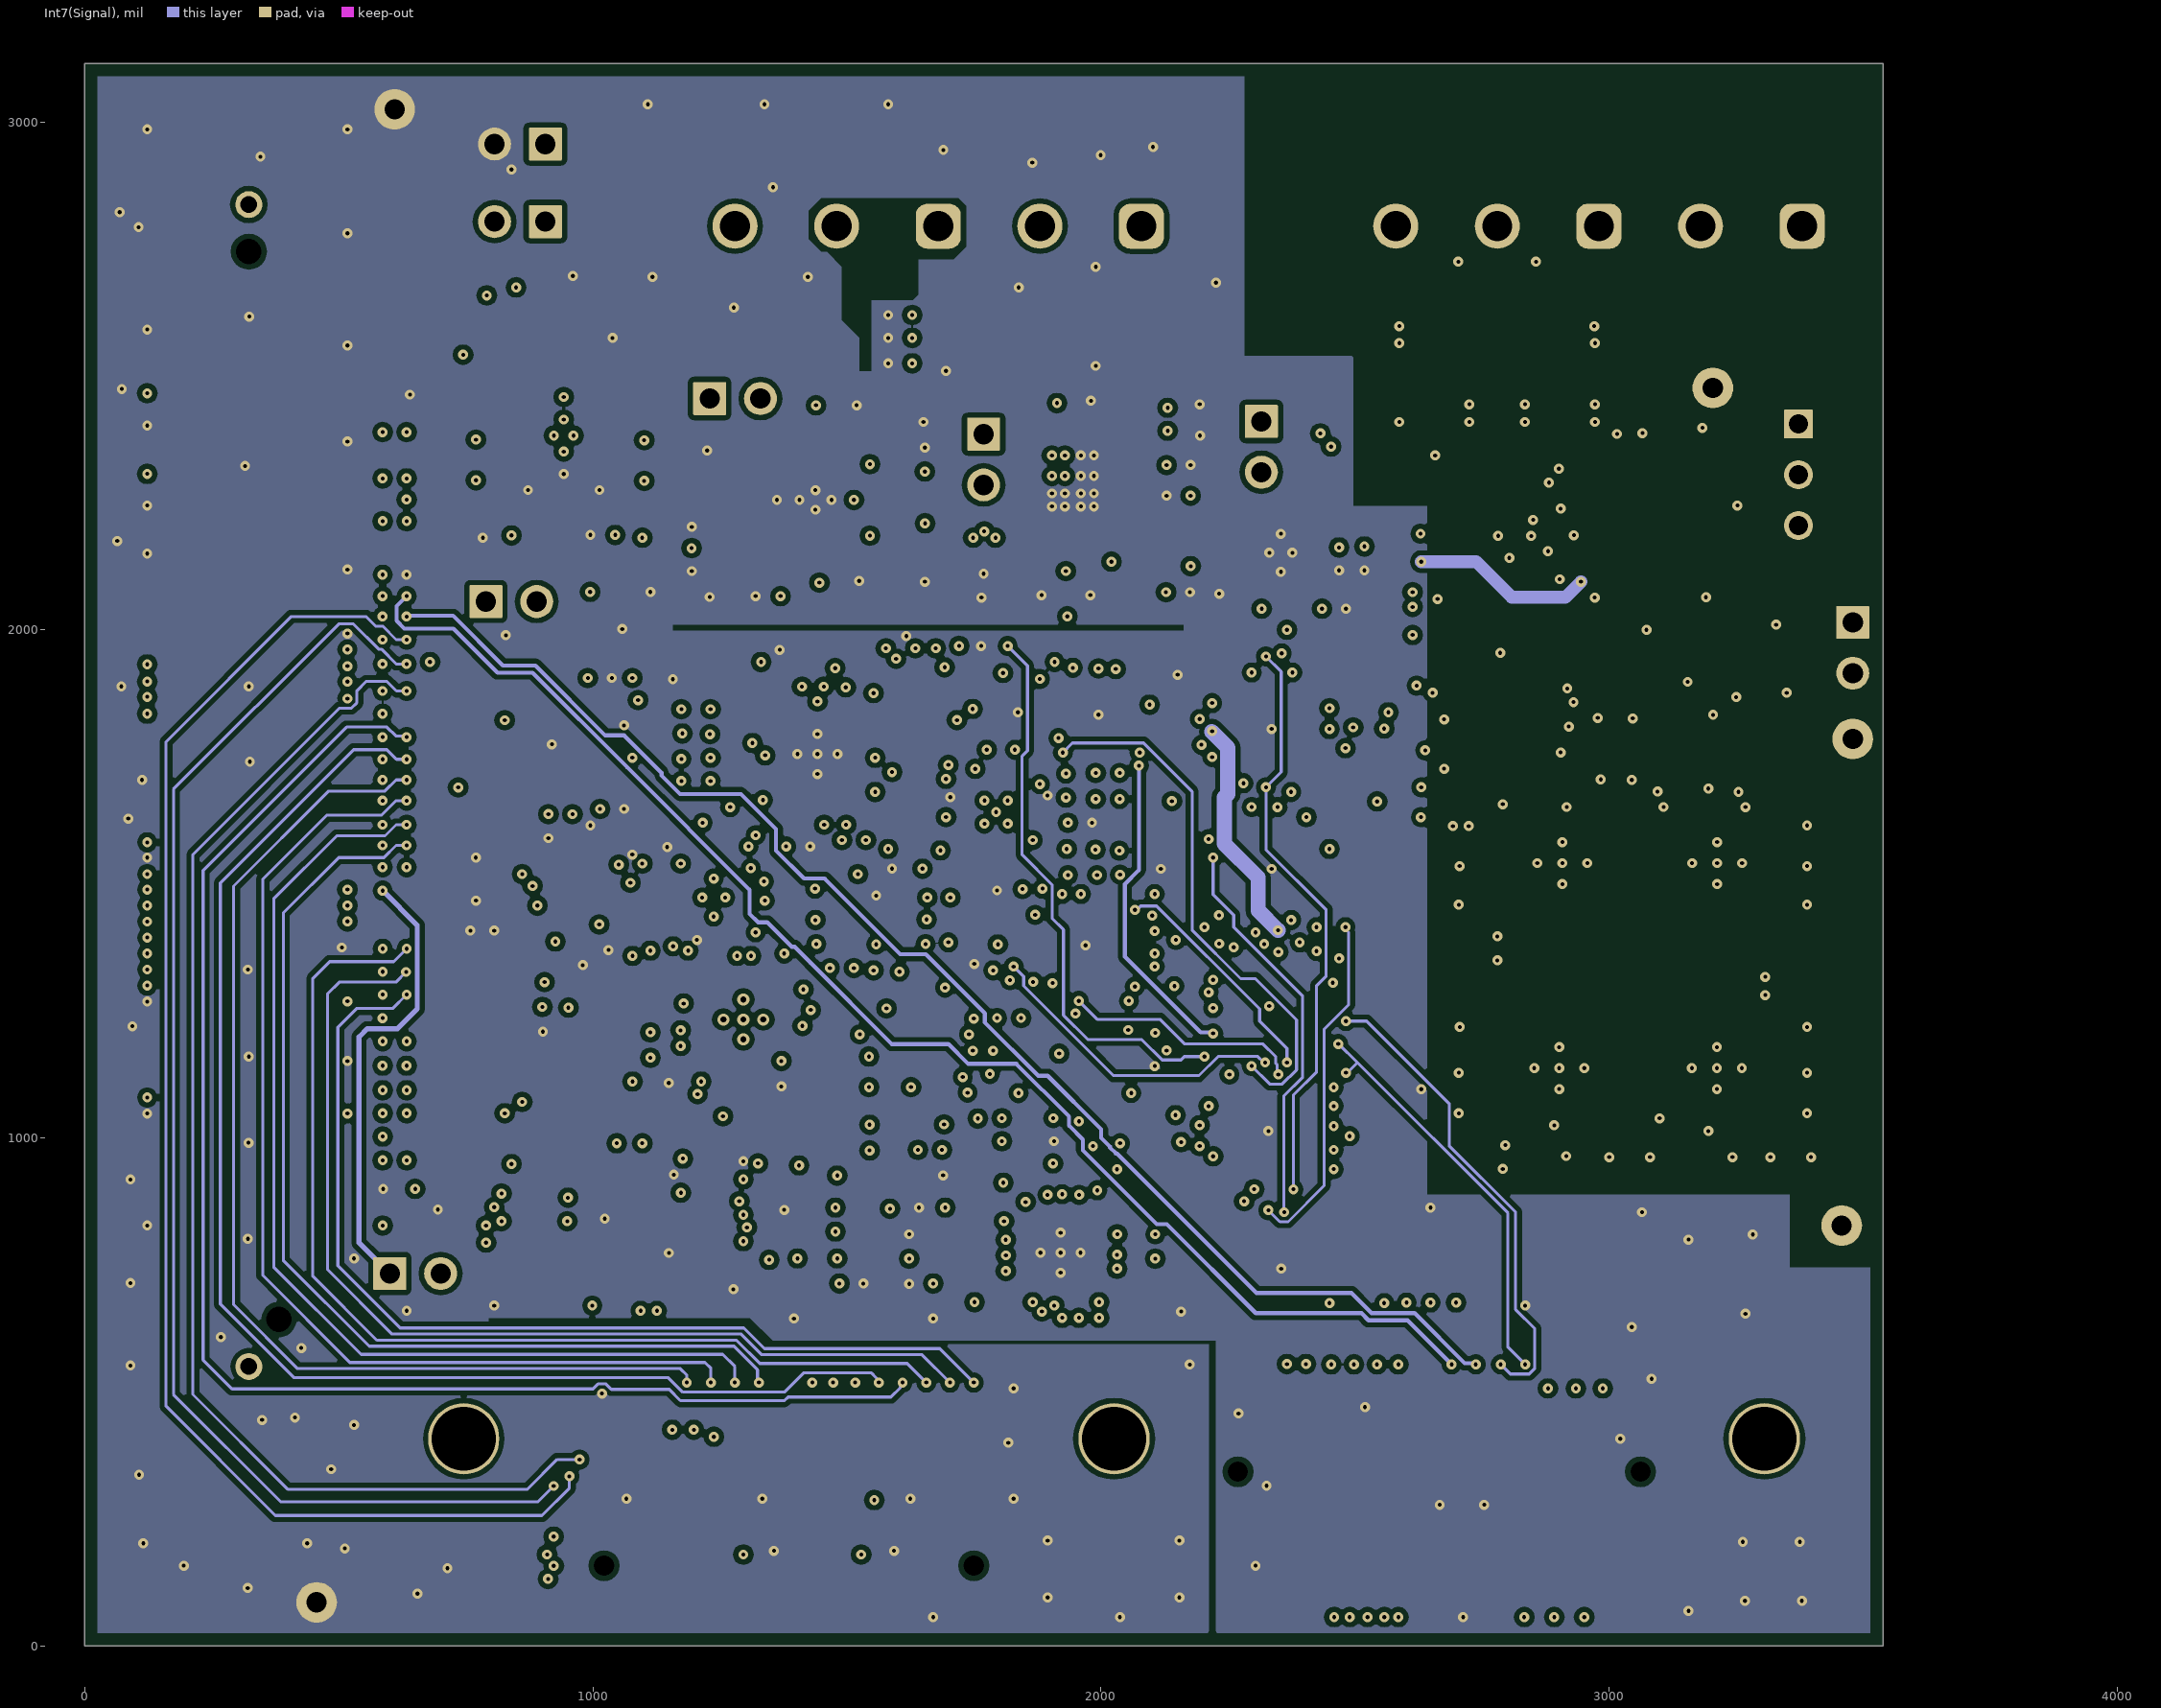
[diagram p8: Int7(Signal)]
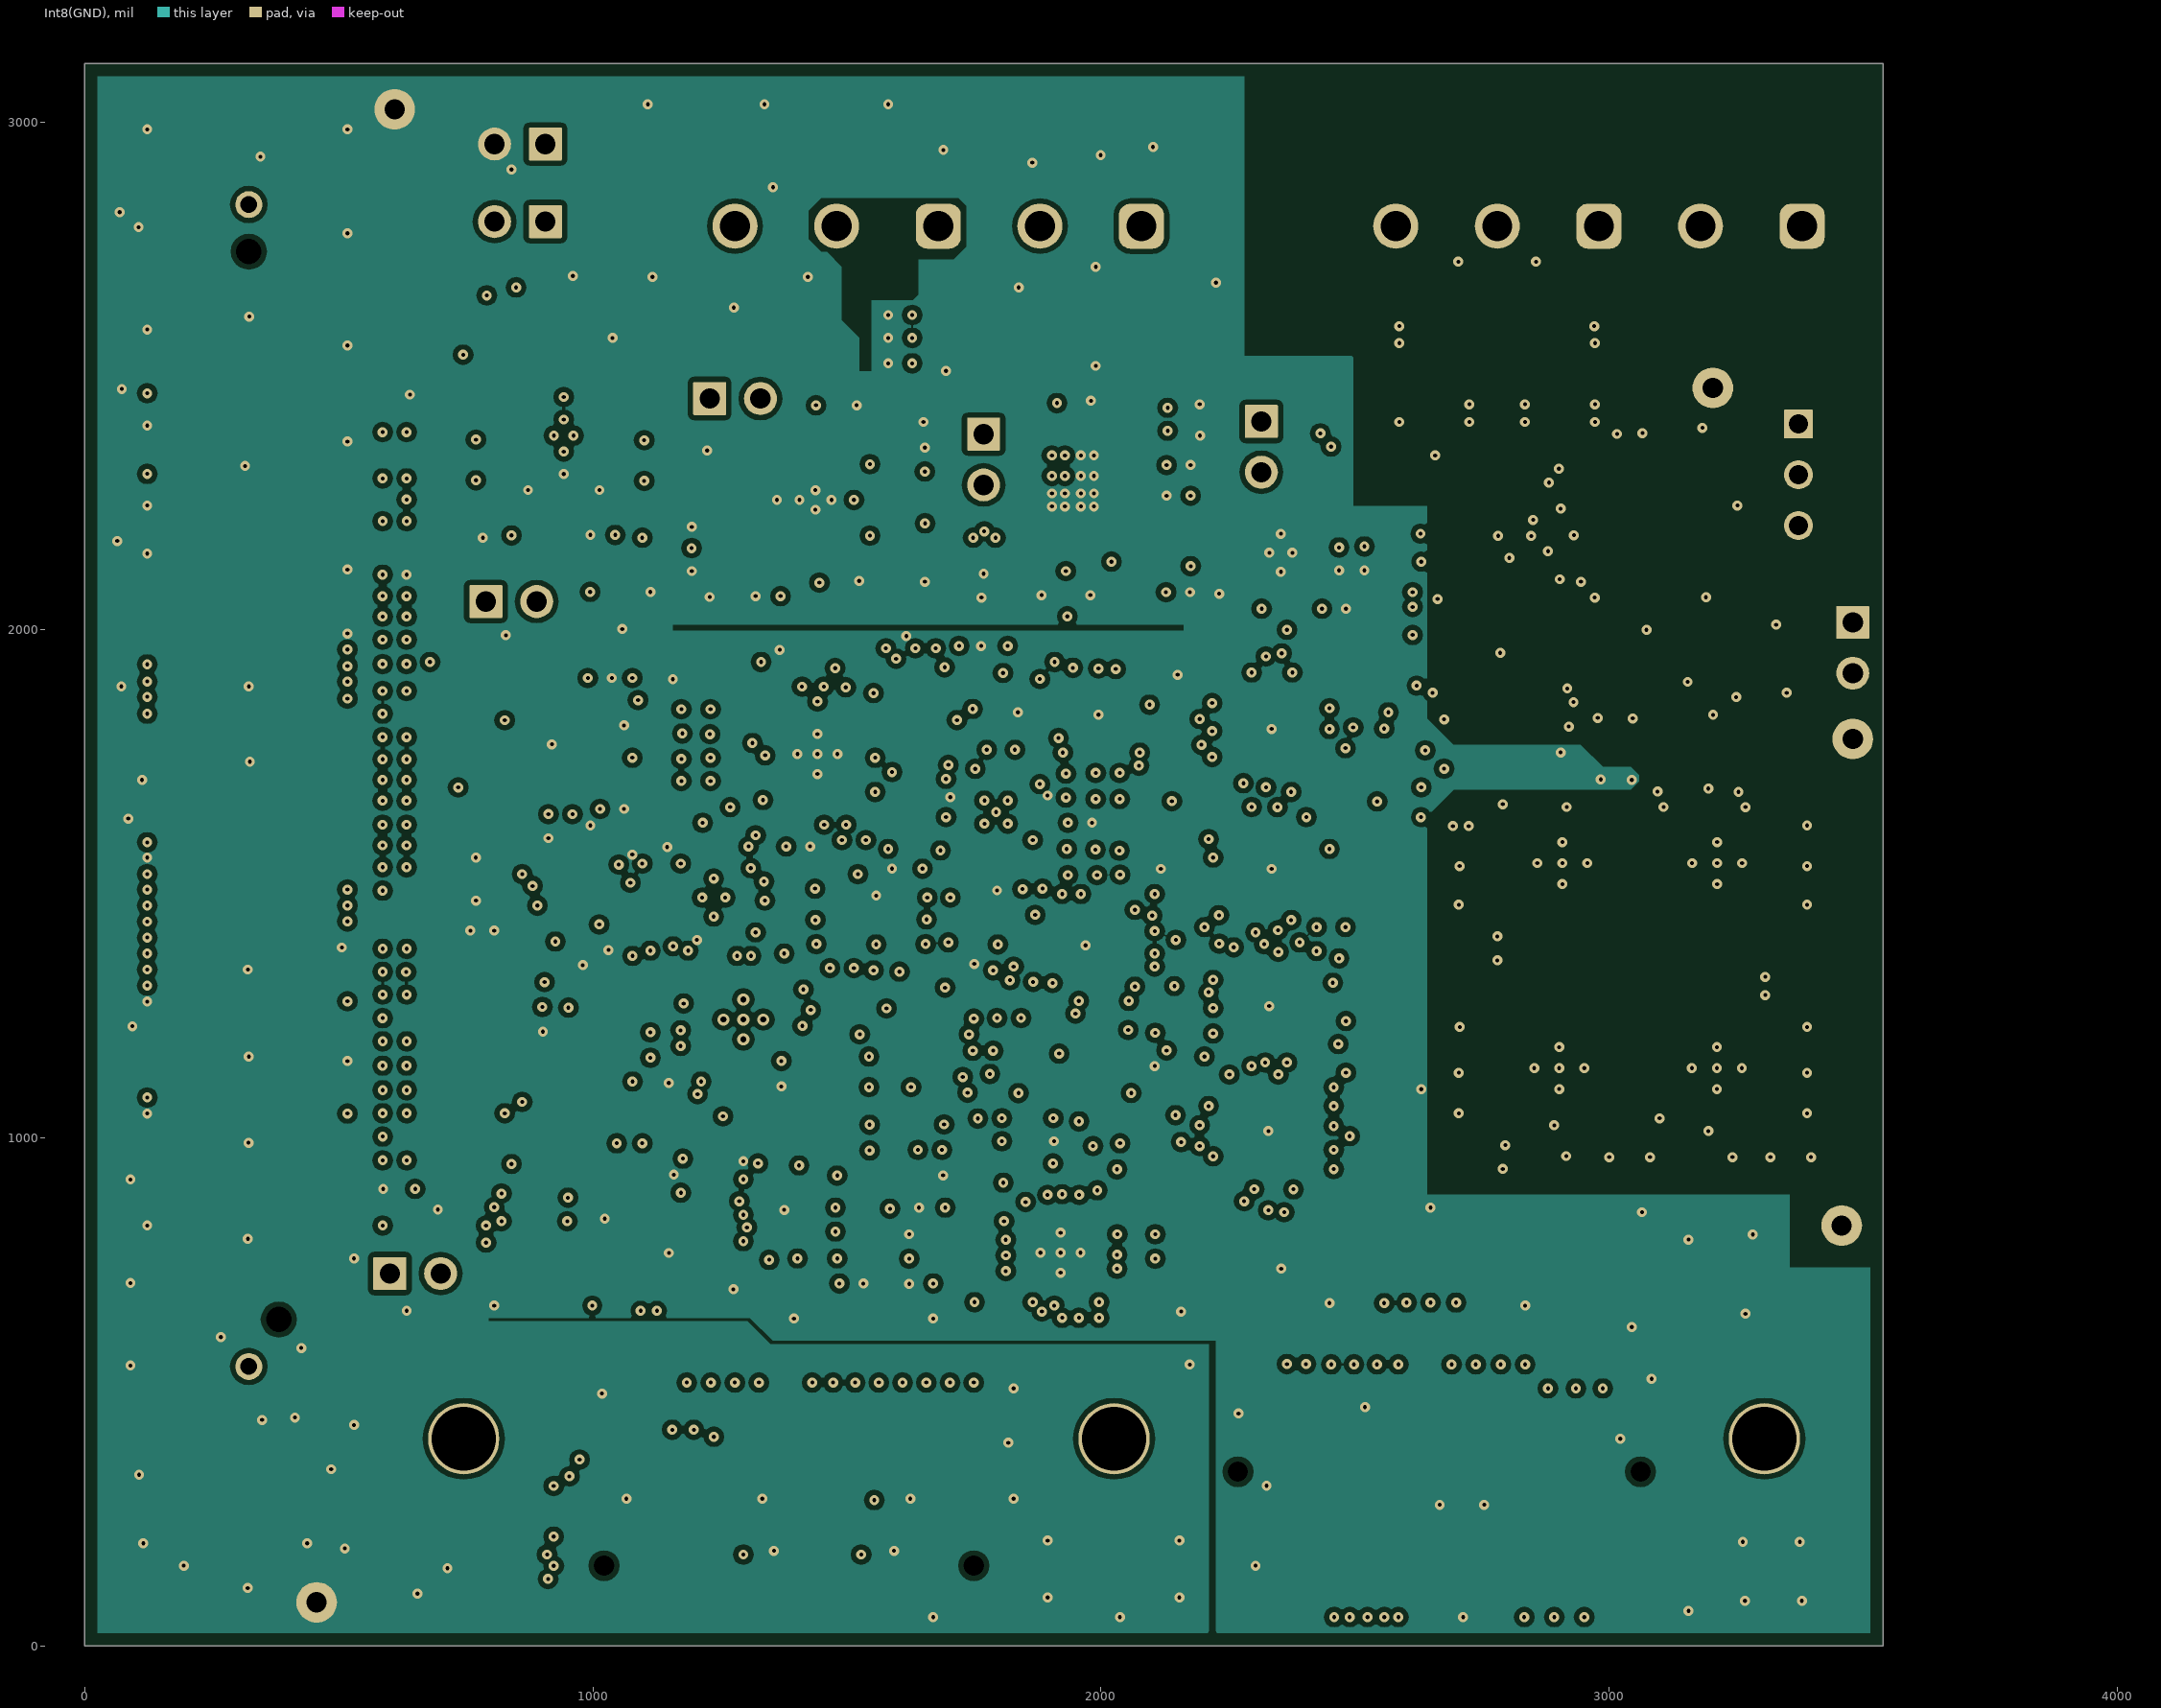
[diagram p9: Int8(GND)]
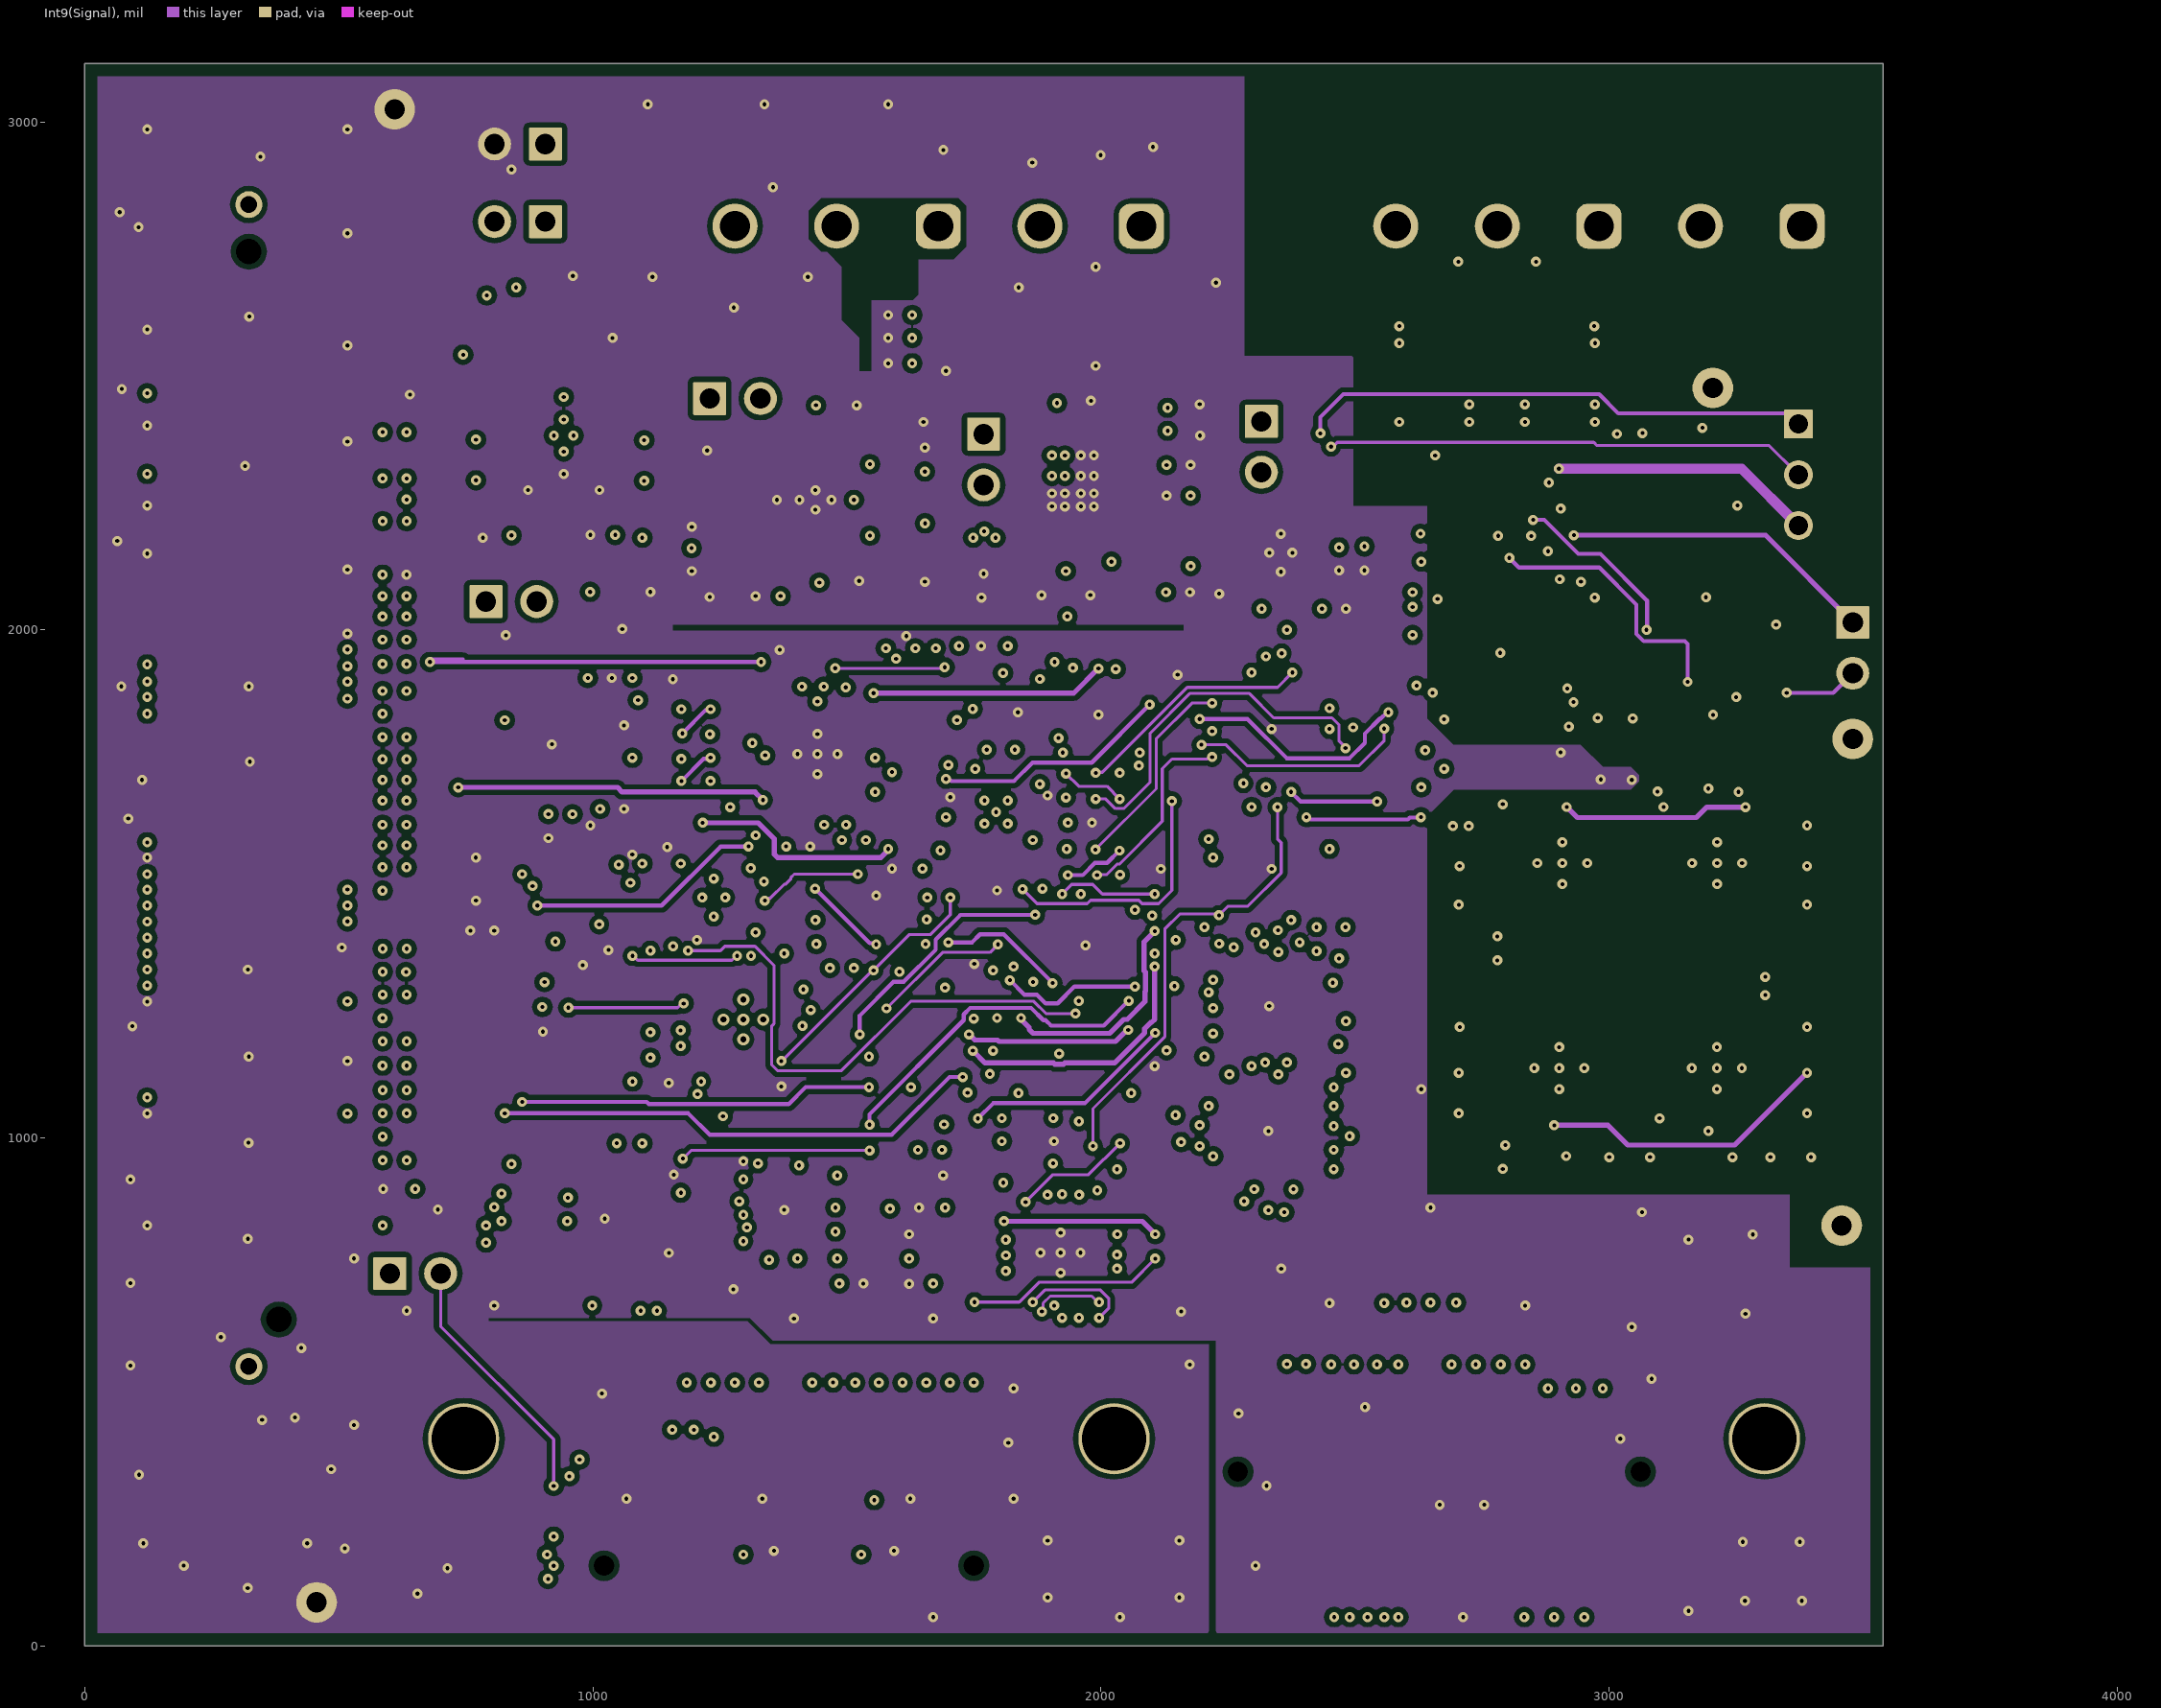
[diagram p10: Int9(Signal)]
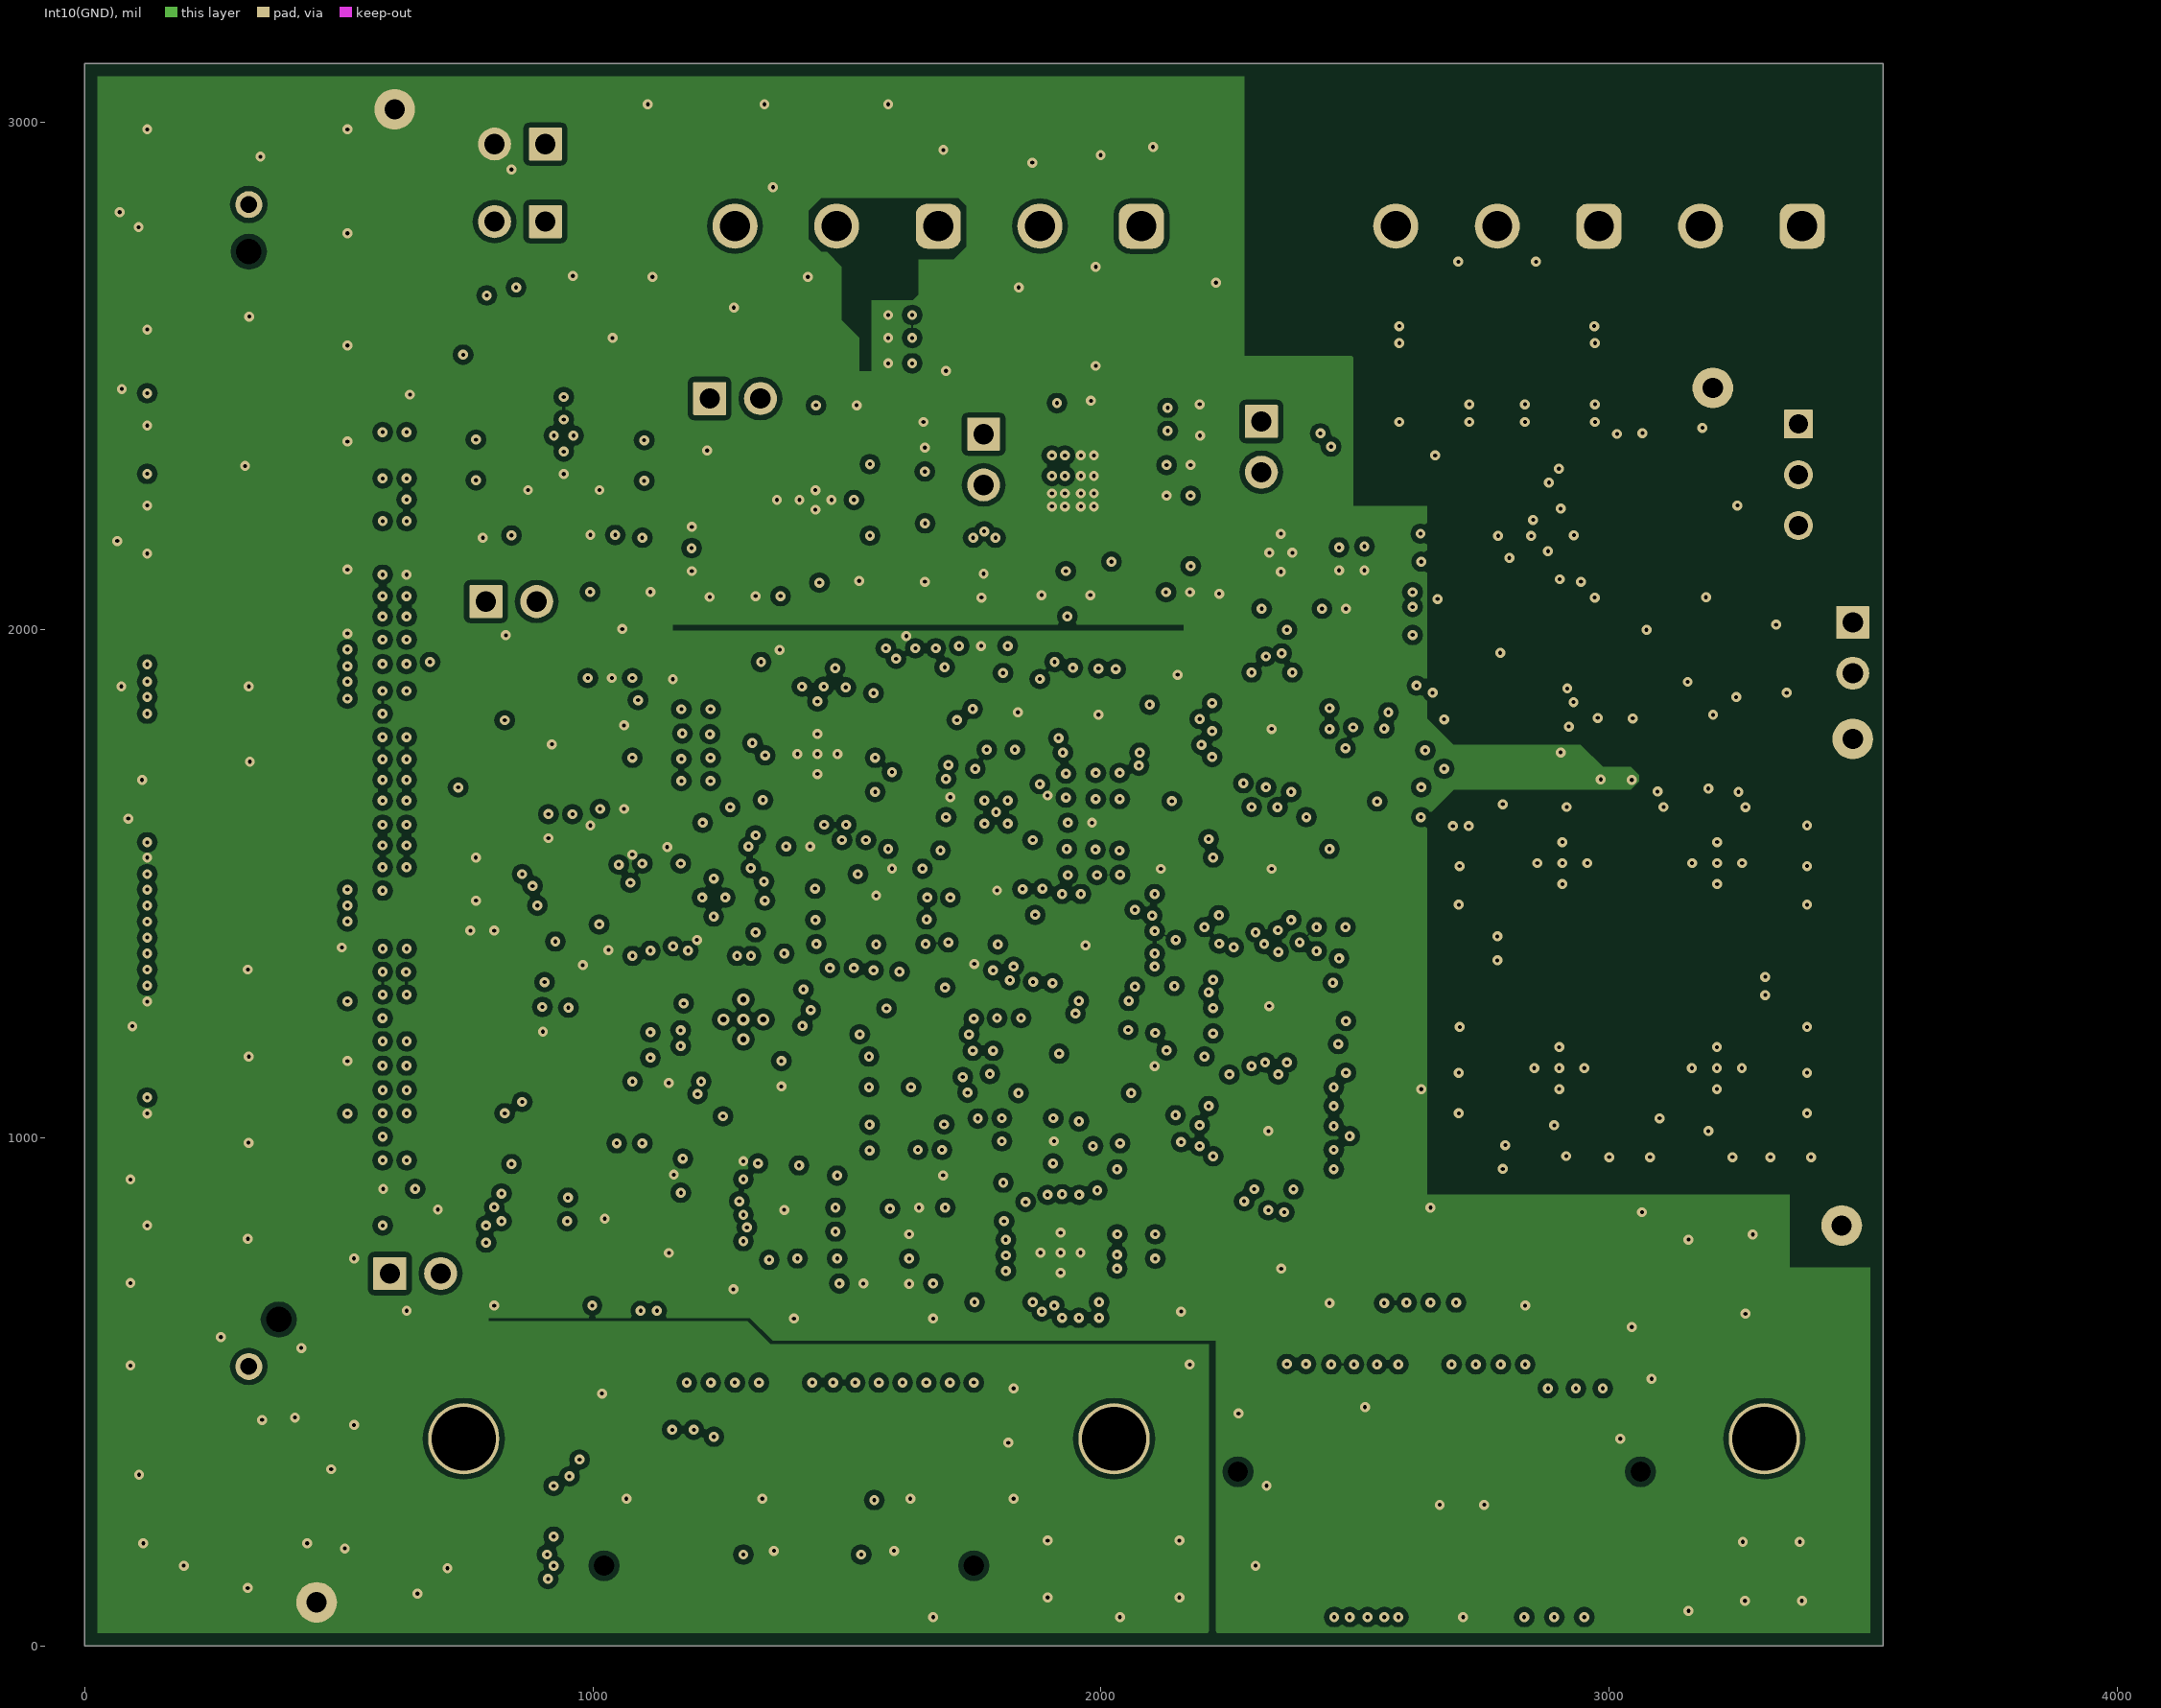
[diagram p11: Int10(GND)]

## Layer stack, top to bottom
Top Solder: solder mask 1, SM-001, Dk 4
Top Layer: signal copper 1.378
Dielectric 2: prepreg 5.1, PP-017, Dk 4.3
Int1(GND): signal copper 1.378
Dielectric 8: prepreg 2.8, PP-006, Dk 4.1
Int2(Signal): signal copper 1.378
Dielectric 6: prepreg 2.8, PP-006, Dk 4.1
Int3(GND): signal copper 1.378
Dielectric 1: prepreg 2.8, PP-006, Dk 4.1
Int4(Signal): signal copper 1.378
Dielectric 10: prepreg 2.8, PP-006, Dk 4.1
Int5 (GND&PW): signal copper 1.378
Dielectric 3: core 28, Core-039, Dk 4.8
Int6 (GND&PW): signal copper 1.378
Dielectric 11: prepreg 2.8, PP-006, Dk 4.1
Int7(Signal): signal copper 1.378
Dielectric 5: prepreg 2.8, PP-006, Dk 4.1
Int8(GND): signal copper 1.378
Dielectric 7: prepreg 2.8, PP-006, Dk 4.1
Int9(Signal): signal copper 1.378
Dielectric 9: prepreg 2.8, PP-006, Dk 4.1
Int10(GND): signal copper 1.378
Dielectric 4: prepreg 5.1, PP-017, Dk 4.3
Bottom Layer: signal copper 1.378
Bottom Solder: solder mask 1, SM-001, Dk 4

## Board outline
0,0 3540,0 3540,3115 0,3115

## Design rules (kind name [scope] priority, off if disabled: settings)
AcuteAngle [All] p1: minimum=4.50000000000000E+0001 checktracksonly=FALSE
AssemblyTestPointUsage [All] p1: valid=2
BoardOutlineClearance BoardOutlineClearance_MountingHoles [OnCopper and InComponentClass('Mounting Holes')] p1: gap=39.37 ignorepadtopadclearanceinfootprint=FALSE
BoardOutlineClearance BoardOutlineClearance_Poly [OnCopper and IsPoly] p2: gap=25 ignorepadtopadclearanceinfootprint=FALSE
BoardOutlineClearance [OnCopper and Not InComponentClass('Logo') and not InComponentClass('FiducialMark') and not InRegion(1000,500,4000,800) and not InPoly] p3: gap=40 ignorepadtopadclearanceinfootprint=FALSE
Clearance Clearance_2 [InNet('VCC_HV_ext') AND InNet('VEE_HV_ext')] p1: gap=10 ignorepadtopadclearanceinfootprint=TRUE
Clearance Clearance_1 [(InNet('PGND') AND (InComponent('T4') OR InComponent('J4')))] p2: gap=10 ignorepadtopadclearanceinfootprint=FALSE except(0: Arc-Hole Track-Hole SMDPad-Hole THPad-Hole Via-Hole Fill-Hole Poly-Hole Region-Hole Text-Hole)
Clearance Clearance_Keepouts [((IsTrack Or IsArc) And Not InPoly) And IsFree and IsKeepOut vs ((IsTrack Or IsArc) And Not InPoly) And IsFree and IsKeepOut] p3: gap=10 ignorepadtopadclearanceinfootprint=FALSE
Clearance Clearance_Poly [InPolygon] p4: gap=10 ignorepadtopadclearanceinfootprint=TRUE
Clearance Clearance_FiducialMark [IsKeepOut and InComponentClass('FiducialMark') vs IsPad and InComponentClass('FiducialMark')] p5: gap=0 ignorepadtopadclearanceinfootprint=FALSE
Clearance [All] p6: gap=6 ignorepadtopadclearanceinfootprint=TRUE
ComponentClearance I/OcomponentClearance [HasFootprint('Johnson_108-0740-001') vs HasFootprint('Panduit_CXS70-14-C')] p1: gap=0 collisioncheckmode=3 verticalgap=0 showdistances=FALSE
ComponentClearance ComponentClearance_MountingHoles_FiducialMarks [InComponentClass('Mounting Holes') vs InComponentClass('FiducialMark')] p2: gap=50 collisioncheckmode=3 verticalgap=10 showdistances=FALSE
ComponentClearance ComponentClearance_Shunt [InComponentClass('Header') vs InComponentClass('Shunt')] p3: gap=0 collisioncheckmode=3 verticalgap=0 showdistances=FALSE
ComponentClearance ComponentClearance_Logo [InComponentClass('Logo')] p4: gap=30 collisioncheckmode=3 verticalgap=10 showdistances=FALSE
ComponentClearance ComponentClearance_ScrewToNut [(HasFootprint('NY PMS 440 0025 PH')) vs (HasFootprint('Keystone_1902C'))] p5: gap=5 collisioncheckmode=3 verticalgap=10 showdistances=FALSE
ComponentClearance ComponentClearance_MountingHoles [InComponentClass('Mounting Holes')] p6: gap=100 collisioncheckmode=3 verticalgap=100000 showdistances=FALSE
ComponentClearance ComponentClearance_SmallPassives [HasFootprint('0201*') or HasFootprint('0402*') or HasFootprint('0508') or HasFootprint('0603*') or HasFootprint('0612') or HasFootprint('0805*') or HasFootprint('0815*') or HasFootprint('0830*') or HasFootprint('1206*') or HasFootprint('1210*') or HasFootprint('1808*') or HasFootprint('1812*') or HasFootprint('1825*') or HasFootprint('2010*') or HasFootprint('2220*') or HasFootprint('2225*') or HasFootprint('2512*') or HasFootprint('2728*') or HasFootprint('3518*') vs HasFootprint('0201*') or HasFootprint('0402*') or HasFootprint('0508') or HasFootprint('0603*') or HasFootprint('0612') or HasFootprint('0805*') or HasFootprint('0815*') or HasFootprint('0830*') or HasFootprint('1206*') or HasFootprint('1210*') or HasFootprint('1808*') or HasFootprint('1812*') or HasFootprint('1825*') or HasFootprint('2010*') or HasFootprint('2220*') or HasFootprint('2225*') or HasFootprint('2512*') or HasFootprint('2728*') or HasFootprint('3518*')] p7: gap=14.96 collisioncheckmode=3 verticalgap=10 showdistances=FALSE
ComponentClearance ComponentClearance_THtoSMT [IsThruComponent vs IsSMTComponent] p8: gap=30 collisioncheckmode=3 verticalgap=30 showdistances=FALSE
ComponentClearance ComponentClearance_THtoTH [IsThruComponent vs IsThruComponent] p9: gap=20 collisioncheckmode=3 verticalgap=30 showdistances=FALSE
ComponentClearance [All] p10: gap=20 collisioncheckmode=3 verticalgap=10 showdistances=FALSE
DiffPairsRouting [All] p1: maxlimit=100 minlimit=6 mostfreqgap=6 toplayer_minwidth=6 toplayer_maxwidth=15 toplayer_prefwidth=6 midlayer1_minwidth=6 midlayer1_maxwidth=15 midlayer1_prefwidth=6 midlayer2_minwidth=6 midlayer2_maxwidth=15 midlayer2_prefwidth=6 midlayer3_minwidth=6 midlayer3_maxwidth=15 midlayer3_prefwidth=6 midlayer4_minwidth=6 midlayer4_maxwidth=15 midlayer4_prefwidth=6 midlayer5_minwidth=6 midlayer5_maxwidth=15 midlayer5_prefwidth=6 midlayer6_minwidth=6 midlayer6_maxwidth=15 midlayer6_prefwidth=6 midlayer7_minwidth=6 midlayer7_maxwidth=15 midlayer7_prefwidth=6 midlayer8_minwidth=6 midlayer8_maxwidth=15 midlayer8_prefwidth=6 midlayer9_minwidth=6 midlayer9_maxwidth=15 midlayer9_prefwidth=6 midlayer10_minwidth=6 midlayer10_maxwidth=15 midlayer10_prefwidth=6 bottomlayer_minwidth=6 bottomlayer_maxwidth=15 bottomlayer_prefwidth=6 maxuncoupledlength=1000
FabricationTestPointUsage TestPointUsage [All] p1: valid=2 allowmultiple=FALSE
FabricationTestpoint Testpoint [All] p1: side=3 testpointundercomponent=TRUE minsize=40 maxsize=100 preferedsize=60 minholesize=0 maxholesize=40 preferedholesize=32 testpointgrid=1 allowsidetop=TRUE allowsidebottom=TRUE usegrid=TRUE gridtolerance=0.01
FanoutControl Fanout_LCC [IsLCC] p1: bgadir=Out bgaviamode=Centered fanoutstyle=Auto fanoutdirection=Alternating viagrid=1 // Fanout_LCC (Default Rule)
FanoutControl Fanout_BGA [IsBGA] p2: bgadir=Out bgaviamode=Centered fanoutstyle=Auto fanoutdirection=Alternating viagrid=1 // Fanout_BGA (Default Rule)
FanoutControl Fanout_Default [All] p4: bgadir=Out bgaviamode=Centered fanoutstyle=Auto fanoutdirection=Alternating viagrid=1 // Fanout_Default (Default Rule)
FanoutControl Fanout_Small [(CompPinCount < 5)] p5: bgadir=Out bgaviamode=Centered fanoutstyle=Auto fanoutdirection=OutThenIn viagrid=1 // Fanout_Small (Default Rule)
Height [All] p1: minheight=0 maxheight=2000 prefheight=500
HoleSize [All] p1: absolutevalues=TRUE maxlimit=350 minlimit=7.87 maxpercent=80.000 minpercent=20.000
HoleToHoleClearance I/OHoleClearance [HasFootprint('Johnson_108-0740-001') vs HasFootprint('Panduit_CXS70-14-C')] p1: gap=0 allowstackedmicrovias=TRUE
HoleToHoleClearance [All] p2: gap=10 allowstackedmicrovias=TRUE
MinimumAnnularRing MinimumAnnularRing_ThermalPadVias [IsVia and InAnyComponent] p1: minimumring=5
MinimumAnnularRing [All] p2: minimumring=5
MinimumSolderMaskSliver MinimumSolderMaskSliver_Logo [InComponentClass('Logo') vs InComponentClass('Logo')] p1: minsoldermaskwidth=0.7
MinimumSolderMaskSliver [All] p2: minsoldermaskwidth=0
PlaneConnect [All] p1: planeconnectstyle=Direct reliefexpansion=10 reliefentries=4 reliefconductorwidth=10 reliefairgap=10
PolygonConnect [All] p1: connectstyle=Direct reliefconductorwidth=10 reliefentries=4 polygonreliefangle="90 Angle" airgapwidth=10
RoutingLayers [All] p1: top layer_v5=TRUE mid layer 1_v5=TRUE mid layer 2_v5=TRUE mid layer 3_v5=TRUE mid layer 4_v5=TRUE mid layer 5_v5=FALSE mid layer 6_v5=FALSE mid layer 7_v5=TRUE mid layer 8_v5=TRUE mid layer 9_v5=TRUE mid layer 10_v5=TRUE bottom layer_v5=TRUE
RoutingVias ThermalPadVias [IsVia and InAnyComponent] p1: holewidth=16 width=32 viastyle="Through Hole" minholewidth=5 minwidth=6 maxholewidth=40 maxwidth=65
RoutingVias [All] p2: holewidth=5 width=32 viastyle="Through Hole" minholewidth=5 minwidth=12 maxholewidth=40 maxwidth=65 viatemplateguid#1={6AFE79DE-537A-4A1D-A782-4CD5BD7B6E79} viatemplateguid#2={8CF40B56-A7D5-42F2-91BD-0217D5440D93} viatemplatename#1=v50h20m0mx0 viatemplatename#2=v56h30m0mx0
SilkToBoardRegionClearance [Not ((IsComment or IsDesignator) And (Hide <> 'False')) and not InRegion(1000,500,4000,800)] p1:
SilkToSilkClearance SilkToSilkClearance_Pb-FreeLogo [(HasFootprint('Pb-Free_Overlay_Medium') OR HasFootprint('Pb-Free_Overlay_Small')) vs (HasFootprint('Pb-Free_Overlay_Medium') OR HasFootprint('Pb-Free_Overlay_Small'))] p1: silktosilkclearance=0
SilkToSilkClearance [All] p2: silktosilkclearance=0
SilkToSolderMaskClearance SilkToComponentPadClearance [All vs IsVia] p1: minsilkscreentomaskgap=0 clearancetoexposedcopper=FALSE
SilkToSolderMaskClearance "Silk to Solder Mask Opening" [Not IsVia vs Not IsVia] p2: minsilkscreentomaskgap=2 clearancetoexposedcopper=FALSE
SolderMaskExpansion [All] p1: expansion=1.97 istentingtop=FALSE
UnRoutedNet [All] p1: checkbadconnections=TRUE
Width [All] p1: maxlimit=100 minlimit=6 preferedwidth=10 checkconnectedcopper=TRUE
11 further rules are at their usual default settings.

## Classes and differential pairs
component class U_FVI80_FPGA_Connector: J8 J14 R131 R139 R140 R214 R215 R216 R217 R218 R219 R220 R221 R222 R223 R224 R225 R226 R227 R228 R231 SH-J6
component class U_FVI80_HV_Power_Connector: C148 C149 C150 H1 H2 H3 J18 J19 R189 R190 R191 R192 R193 R194 R195 R196 R197 R198 R199 R200 R201 R202 R203 R204 R205 R206 R207 R208 R209
component class U_FVI80_Signal_DAC: C46 C47 C48 C49 C50 C51 C52 C53 C54 C55 C56 C57 C58 C59 C60 C61 C62 C63 C64 C65 C66 C67 C68 C69 C70 C71 C72 R115 R116 R117 R118 R119 R120 R121 R122 R123 R124 R125 R126 R127 R128 R129 R232 R233 R234 TP5 TP6 U27 U28 U29 U30 U31 U32 U33 U44
component class U_FVI80_Signal_CCCV: C19 C20 C21 C22 C23 C24 C25 C26 C27 C28 C29 C30 C31 C32 C33 C34 C35 C36 C37 C38 C39 C40 C41 D5 J4 R48 R49 R50 R51 R52 R53 R54 R55 R56 R57 R58 R59 R60 R61 R62 R63 R64 R65 R66 R67 R68 R69 R70 R71 R75 R76 R77 R78 R79 R80 R81 R82 R86 R87 R88 R89 R90 R91 R92 R93 R94 R95 R99 R100 R103 R104 R105 R106 R107 R108 R109 R110 R111 R112 R113 R130 R229 R230 RN2 RN3 U8 U9 U10 U11 U12 U13 U14 U15 U16 U17 U18 U19 U20 U21 U22 U39
component class U_FVI80_Signal_biasPower: C99 C100 C101 C102 C103 C104 C105 C106 C107 C108 C109 C110 C111 C112 C113 C114 C115 C116 C117 C118 C119 C120 C121 C122 C123 C124 C125 C126 C127 C128 C129 C130 C131 C132 C133 C134 C135 C136 C137 C138 C139 FB1 FB2 J5 J6 J7 J9 J10 J11 J12 J13 R147 R148 R149 R150 R151 R152 R153 R154 R155 R156 R157 R158 R159 R160 R161 R162 SH-J1 SH-J2 SH-J3 SH-J4 SH-J5 U40 U41 U42 U43
component class U_FVI80_Signal_ADC93: C75 C76 C77 C78 C79 C80 C85 C86 C87 C88 C89 C90 C91 C92 C93 C94 C95 C96 C97 C98 C151 C152 R132 R133 R134 R135 R136 R137 R138 R141 R142 R143 R144 R145 R146 RN6 RN7 U34 U35 U36 U37 U38
component class U_FVI80_Power_Rsense_series: 22 C9 C10 C11 C12 C13 C14 C15 C16 C17 C18 C140 C141 C142 C143 D1 D2 D3 D4 J1 J2 J3 K1 K2 K3 K4 K5 K6 K7 K8 K9 R22 R23 R24 R25 R26 R27 R28 R29 R30 R31 R32 R33 R34 R35 R36 R37 R38 R39 R40 R41 R42 R43 R44 R45 R46 R47 R210 R211 R212 R213 RN1 TP1 TP2 TP3 U5 U6 U7
component class U_FVI80_Power_OPA593: C1 C2 C3 C4 C5 C6 C7 C8 R1 R2 R3 R4 R5 R6 R7 R8 R9 R10 R11 R12 R13 R14 R15 R16 R17 R18 R19 R20 R21 R72 R73 R74 R83 R84 R85 R96 R97 R98 R101 R102 U1 U2 U3 U4
component class U_FVI80_MUX_Signal: C42 C43 C44 C45 R114 U23 U24 U25 U26
component class U_FVI80_ME: !PCB1 FID1 FID2 FID3 FID4 FID5 FID6 LBL1 Logo1 Logo2 Logo3 Logo4
component class U_FVI80_C2000_Connector: C144 C145 C146 C147 D8 J17 R163 R164 R165 R166 R167 R168 R169 R170 R171 R172 R173 R174 R175 R176 R177 R178 R179 R180 R181 R182 R183 R184 R185 R186 R187 R188

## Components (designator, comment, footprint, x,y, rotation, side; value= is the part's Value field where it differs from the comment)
C1 "GRM155R62A104KE14D" 0402 3284,1281.42 r180 bottom value=0.1uF
C2 "GRM155R62A104KE14D" 0402 3100.81,1480.46 r270 bottom value=0.1uF
C3 "GRM155R62A104KE14D" 0402 3329,1062.82 r90 bottom value=0.1uF
C4 "GRM155R62A104KE14D" 0402 2779.54,1574.5 r270 bottom value=0.1uF
C5 "GRM155R62A104KE14D" 0402 3073,1177 r90 bottom value=0.1uF
C6 "GRM155R62A104KE14D" 0402 2780.34,1373.28 r90 bottom value=0.1uF
C7 "GRM155R62A104KE14D" 0402 3027,1080.31 r90 bottom value=0.1uF
C8 "GRM155R62A104KE14D" 0402 3329,1597 r270 bottom value=0.1uF
C9 "12061Z475MAT2A" 1206_190 2880,2905 r180 bottom value=4.7uF
C10 "GRM155R62A104KE14D" 0402 2880,2725 r180 bottom value=0.1uF
C11 "GRM155R62A104KE14D" 0402 2909.45,2439.33 r180 bottom value=0.1uF
C12 "GRM155R72A222KA01D" 0402 2909.45,2387.6 r180 bottom value=2200pF
C13 "12061Z475MAT2A" 1206_190 2903.62,2425 r180 top value=4.7uF
C14 "12061Z475MAT2A" 1206_190 2670,2905 r180 bottom value=4.7uF
C15 "GRM155R62A104KE14D" 0402 2680,2725 r180 bottom value=0.1uF
C16 "GRM155R62A104KE14D" 0402 2651,2439.33 r180 bottom value=0.1uF
C17 "GRM155R72A222KA01D" 0402 2651,2387.6 r180 bottom value=2200pF
C18 "12061Z475MAT2A" 1206_190 2656.38,2425 r180 top value=4.7uF
C19 "GRM1555C1H270JA01D" 0402 1740.97,1520.34 r180 bottom value=27pF
C20 "GRM1555C1H270JA01D" 0402 1750.88,1366.4 r90 bottom value=27pF
C21 "CGA2B3X7R1E104K050BB" 0402 1646.42,810.51 r0 bottom value=0.1uF
C22 "CGA2B3X7R1E104K050BB" 0402 1717,1296 r180 bottom value=0.1uF
C23 "CGA2B3X7R1E104K050BB" 0402 1665.71,862.89 r0 bottom value=0.1uF
C24 "CGA2B3X7R1E104K050BB" 0402 2059.06,1113.13 r270 bottom value=0.1uF
C25 "CGA2B3X7R1E104K050BB" 0402 1958.92,1620.51 r180 bottom value=0.1uF
C26 "CGA2B3X7R1E104K050BB" 0402 1962.32,1616.97 r180 top value=0.1uF
C27 "GRM1555C1H270JA01D" 0402 1931.42,1693.79 r270 bottom value=27pF
C28 "GRM1555C1H270JA01D" 0402 1838.55,1520.34 r0 bottom value=27pF
C29 "CGA2B3X7R1E104K050BB" 0402 1814.93,1283.12 r180 bottom value=0.1uF
C30 "CGA2B3X7R1E104K050BB" 0402 1838,1807 r0 bottom value=0.1uF
C31 "CGA2B3X7R1E104K050BB" 0402 1481.07,949.7 r90 bottom value=0.1uF
C32 "CGA2B3X7R1E104K050BB" 0402 1835.97,1880 r90 bottom value=0.1uF
C33 "CGA2B3X7R1E104K050BB" 0402 1646.8,1698.71 r90 top value=0.1uF
C34 "CGA2B3X7R1E104K050BB" 0402 1646.8,1791.43 r90 top value=0.1uF
C35 "GRM1555C1H270JA01D" 0402 1466.57,1265.55 r90 bottom value=27pF
C36 "GRM1555C1H270JA01D" 0402 1751.82,1764.22 r180 top value=27pF
C37 "GRM1555C1H270JA01D" 0402 1854.45,1764.22 r0 top value=27pF
C38 "GRM1555C1H270JA01D" 0402 1935.3,1541.17 r90 bottom value=27pF
C39 "CGA2B2X8R1H102K050BA" 0402 2064.51,731.9 r90 top value=1000pF
C40 "GRM155R71H103KA88D" 0402 1776.09,741.28 r90 top value=0.01uF
C41 "GRM155R61E474KE01D" 0402 1776.42,839.31 r270 top value=0.47uF
C42 "CGA2B3X7R1E104K050BB" 0402 2274.5,1797.63 r180 bottom value=0.1uF
C43 "CGA2B3X7R1E104K050BB" 0402 2231,1123 r0 bottom value=0.1uF
C44 "CGA2B3X7R1E104K050BB" 0402 2424.55,1293.64 r90 bottom value=0.1uF
C45 "CGA2B3X7R1E104K050BB" 0402 2212.13,1611.99 r90 top value=0.1uF
C46 "GRM1555C1H270JA01D" 0402 1245.28,801.73 r90 bottom value=27pF
C47 "GRM155R61A106ME11D" 0402 1089.74,1208.02 r180 bottom value=10uF
C48 "CGA2B3X7R1E104K050BB" 0402 1089.74,1158.02 r0 bottom value=0.1uF
C49 "CGA2B3X7R1E104K050BB" 0402 901.83,1233.02 r90 bottom value=0.1uF
C50 "GRM155R61A106ME11D" 0402 952.03,1233.02 r270 bottom value=10uF
C51 "GRM155R61A106ME11D" 0402 928.71,1306.88 r0 bottom value=10uF
C52 "GRM1555C1H270JA01D" 0402 1246.34,907.7 r270 bottom value=27pF
C53 "GRM1555C1H270JA01D" 0402 1149.8,845.65 r180 bottom value=27pF
C54 "GRM155R61A106ME11D" 0402 1404.21,1573.88 r0 top value=10uF
C55 "CGA2B3X7R1E104K050BB" 0402 1404.21,1573.88 r180 bottom value=0.1uF
C56 "GRM1555C1H270JA01D" 0402 1477.64,839.31 r270 bottom value=27pF
C57 "CGA2B3X7R1E104K050BB" 0402 975.54,1410.47 r270 bottom value=0.1uF
C58 "GRM155R61A106ME11D" 0402 926.36,1410.47 r90 bottom value=10uF
C59 "CGA2B3X7R1E104K050BB" 0402 1097.41,771 r270 bottom value=0.1uF
C60 "CGA2B3X7R1E104K050BB" 0402 1627.3,1529.36 r0 bottom value=0.1uF
C61 "CGA2B3X7R1E104K050BB" 0402 1215.65,1189.08 r90 bottom value=0.1uF
C62 "CGA2B3X7R1E104K050BB" 0402 1133.43,1502.3 r270 top value=0.1uF
C63 "CGA2B3X7R1E104K050BB" 0402 998.98,771 r270 bottom value=0.1uF
C64 "CGA2B3X7R1E104K050BB" 0402 1094.82,1406.73 r180 bottom value=0.1uF
C65 "GRM155R61A106ME11D" 0402 1764.26,1945 r90 bottom value=10uF
C66 "CGA2B3X7R1E104K050BB" 0402 1047.21,771 r90 bottom value=0.1uF
C67 "CGA2B3X7R1E104K050BB" 0402 1509.02,713.55 r0 bottom value=0.1uF
C68 "CGA2B3X7R1E104K050BB" 0402 1394.78,1194 r180 bottom value=0.1uF
C69 "CGA2B3X7R1E104K050BB" 0402 1463.53,1381.72 r0 bottom value=0.1uF
C70 "GRM155R61A106ME11D" 0402 926.15,983.67 r0 bottom value=10uF
C71 "CGA2B3X7R1E104K050BB" 0402 925.16,939.53 r180 bottom value=0.1uF
C72 "CGA2B3X7R1E104K050BB" 0402 1721,1945 r90 bottom value=0.1uF
C75 "GRM155R61A106ME11D" 0402 877.04,1798.78 r270 bottom value=10uF
C76 "CGA2B3X7R1E104K050BB" 0402 919.51,1798.78 r90 bottom value=0.1uF
C77 "GRM155R61A106ME11D" 0402 912.78,1613.9 r270 top value=10uF
C78 "CGA2B3X7R1E104K050BB" 0402 912.78,1613.9 r90 bottom value=0.1uF
C79 "GRM155R61A106ME11D" 0402 1037.9,1647.79 r0 bottom value=10uF
C80 "CGA2B3X7R1E104K050BB" 0402 1037.9,1647.79 r180 top value=0.1uF
C85 "CGA2B3X7R1E104K050BB" 0402 1517.07,1726.44 r90 bottom value=0.1uF
C86 "CGA2B2X8R1H102K050BA" 0402 1255.47,1796.35 r0 bottom value=1000pF
C87 "CGA2B3X7R1E104K050BB" 0402 1176.31,1822.53 r90 bottom value=0.1uF
C88 "CGA2B2X8R1H102K050BA" 0402 1255.47,1844.19 r180 bottom value=1000pF
C89 "CGA2B3X7R1E104K050BB" 0402 1461.95,1837.66 r180 bottom value=0.1uF
C90 "GRM155R61A106ME11D" 0402 1005.22,1730.44 r180 bottom value=10uF
C91 "CGA2B2X8R1H102K050BA" 0402 1013.85,1905.44 r0 bottom value=1000pF
C92 "CGA2B3X7R1E104K050BB" 0402 1013.85,1905.44 r180 top value=0.1uF
C93 "GRM155R61A106ME11D" 0402 1005.22,1840.44 r0 bottom value=10uF
C94 "CGA2B2X8R1H102K050BA" 0402 1597.62,1791.25 r90 top value=1000pF
C95 "CGA2B2X8R1H102K050BA" 0402 1255.47,1702.73 r0 bottom value=1000pF
C96 "CGA2B3X7R1E104K050BB" 0402 1176.31,1724.39 r90 bottom value=0.1uF
C97 "CGA2B2X8R1H102K050BA" 0402 1255.47,1748.55 r180 bottom value=1000pF
C98 "CGA2B2X8R1H102K050BA" 0402 1476.33,1888.53 r0 top value=1000pF
C99 "CGA3E1X7R1V105K080AE" 0603 1225.08,2322 r90 top value=1uF
C100 "C3216JB1E476M160AC" 1206 1653.53,2352.4 r90 top value=47uF
C101 "C3216JB1E476M160AC" 1206 1653.53,2152.03 r270 top value=47uF
C102 "CGA2B3X7R1E104K050BB" 0402 1653.53,2335.55 r90 bottom value=0.1uF
C103 "GRT21BR61E226ME13L" 0805_HV 1769.3,2150.89 r270 bottom value=22uF
C104 "CGA2B3X7R1E104K050BB" 0402 1699.79,2168.44 r270 bottom value=0.1uF
C105 "CGA2B2X8R1H102K050BA" 0402 1748.8,2158.13 r270 top value=1000pF
C106 "GRM155R71H103KA88D" 0402 1792.58,2158.13 r270 top value=0.01uF
C107 "GRT21BR61E226ME13L" 0805_HV 1580,2685.95 r180 bottom value=22uF
C108 "GRM155R71H103KA88D" 0402 1605,2525 r180 bottom value=0.01uF
C109 "CGA2B2X8R1H102K050BA" 0402 1605,2575 r180 bottom value=1000pF
C110 "CL10A226MO7JZNC" 0603 1948.12,2449.71 r0 bottom value=22uF
C111 "CL10A226MO7JZNC" 0603 2163.01,2444.25 r0 top value=22uF
C112 "CL10A226MO7JZNC" 0603 1948.12,2449.71 r0 top value=22uF
C113 "CL10A226MO7JZNC" 0603 2163.64,2382.62 r0 top value=22uF
C114 "CGA2B3X7R1E104K050BB" 0402 2153.01,2324.68 r0 top value=0.1uF
C115 "CGA2B2X8R1H102K050BA" 0402 2153.01,2324.68 r0 bottom value=1000pF
C116 "GRM155R61A106ME11D" 0402 2151.81,2074.47 r0 bottom value=10uF
C117 "CGA2B3X7R1E104K050BB" 0402 2151.81,2074.47 r0 top value=0.1uF
C118 "GRM155R61A106ME11D" 0402 2153.01,2264.33 r180 top value=10uF
C119 "CGA2B3X7R1E104K050BB" 0402 2153.01,2264.33 r180 bottom value=0.1uF
C120 "CGA2B3X7R1E104K050BB" 0402 1883.39,2092.32 r90 top value=0.1uF
C121 "CGA3E1X7R1V105K080AE" 0603 849,2642.95 r90 top value=1uF
C122 "CGA2B2X8R1H102K050BA" 0402 1020.52,2187.14 r0 bottom value=1000pF
C123 "C3216JB1E476M160AC" 1206 1051.16,2075 r180 bottom value=47uF
C124 "CGA2B3X7R1E104K050BB" 0402 1018.26,2075 r180 top value=0.1uF
C125 "C3216JB1E476M160AC" 1206 840.66,2181.67 r0 top value=47uF
C126 "C3216JB1E476M160AC" 1206 1042.86,2181.24 r0 top value=47uF
C127 "CGA2B3X7R1E104K050BB" 0402 863.62,2186.16 r180 bottom value=0.1uF
C128 "GRM155R61A106ME11D" 0402 2518.79,2140.87 r270 bottom value=10uF
C129 "CGA2B3X7R1E104K050BB" 0402 2468.79,2140.87 r270 top value=0.1uF
C130 "CGA2B2X8R1H102K050BA" 0402 2468.79,2140.87 r270 bottom value=1000pF
C131 "CGA2B3X7R1E104K050BB" 0402 2233.01,2095.16 r270 top value=0.1uF
C132 "GRT21BR61E226ME13L" 0805_HV 1169,2854 r270 bottom value=22uF
C133 "GRM155R71H103KA88D" 0402 1605,2620 r180 bottom value=0.01uF
C134 "CGA2B2X8R1H102K050BA" 0402 1099.95,2848 r270 bottom value=1000pF
C135 "C2012X6S1H475K125AC" 0805_HV 1101.23,2333.58 r270 top value=4.7uF
C136 "C2012X6S1H475K125AC" 0805_HV 770,2334.8 r270 top value=4.7uF
C137 "GRM155R61A106ME11D" 0402 2458.79,2042.03 r0 top value=10uF
C138 "GRT21BR61E226ME13L" 0805_HV 1484.16,2096.65 r0 top value=22uF
C139 "GRT21BR61E226ME13L" 0805_HV 1479.39,2442.3 r0 top value=22uF
C140 "12061Z475MAT2A" 1206_190 2903.62,2585 r0 bottom value=4.7uF
C141 "GRM155R62A104KE14D" 0402 2827.1,2484.27 r270 bottom value=0.1uF
C142 "12061Z475MAT2A" 1206_190 2656.38,2585 r0 bottom value=4.7uF
C143 "GRM155R62A104KE14D" 0402 2731.99,2484.27 r90 bottom value=0.1uF
C144 "CGA2B3X7R1E104K050BB" 0402 610,2108.97 r180 top value=0.1uF
C145 "CGA2B3X7R1E104K050BB" 0402 610,1236 r180 top value=0.1uF
C146 "CGA2B3X7R1E104K050BB" 0402 610.12,1002.85 r180 top value=0.1uF
C147 "CGA2B3X7R1E104K050BB" 0402 610.12,827.68 r180 top value=0.1uF
C148 "CGA2B3X7R1E104K050BB" 0402 2987.92,530.72 r90 top value=0.1uF
C149 "CGA2B3X7R1E104K050BB" 0402 2935,530.72 r90 top value=0.1uF
C150 "CGA2B3X7R1E104K050BB" 0402 2880.05,530.72 r90 top value=0.1uF
C151 "CGA2B2X8R1H102K050BA" 0402 1477,1616.59 r0 top value=1000pF
C152 "CGA2B2X8R1H102K050BA" 0402 1597.62,1698.71 r270 top value=1000pF
D1 "BZB784-C9V1,115" SOT-323 2950.17,2264.33 r180 bottom value=9.1V
D2 "BZB784-C9V1,115" SOT-323 2822.73,1779.53 r90 bottom value=9.1V
D3 "BZB784-C9V1,115" SOT-323 3070,2305 r270 bottom value=9.1V
D4 "BZB784-C9V1,115" SOT-323 3205,2298 r270 top value=9.1V
D5 "SBAV99WT1G" FP-SBAV99WT1G_SOT-323-3-419-04-MFG 1578.09,1292.53 r270 bottom
D8 "150060VS75000" WL-SMCW_GREEN 619,899.83 r0 top value=Green
FB1 "7427927311" 0402 2131.51,2415.71 r270 bottom value="120 ohm"
FB2 "7427927311" 0402 2153.15,2125.65 r180 top value="120 ohm"
FID1 "Fiducial" Fiducial10-20 70,3044 r90 bottom
FID2 "Fiducial" Fiducial10-20 3463,69 r180 bottom
FID3 "Fiducial" Fiducial10-20 70,69 r90 bottom
FID4 "Fiducial" Fiducial10-20 70,69 r90 top
FID5 "Fiducial" Fiducial10-20 3463,69 r90 top
FID6 "Fiducial" Fiducial10-20 70,3044 r180 top
H1 "NY PMS 440 0025 PH" "NY PMS 440 0025 PH" 2026,408 r0 top
H2 "NY PMS 440 0025 PH" "NY PMS 440 0025 PH" 3306,408 r0 top
H3 "NY PMS 440 0025 PH" "NY PMS 440 0025 PH" 746,408 r0 top
J1 "691236510002" Wurth_691236510002 3280.34,2795 r180 top
J2 "691236510003" Wurth_691236510003 2780.34,2795 r180 top
J3 "HTSW-102-07-G-S" Samtec_HTSW-102-07-G-S 3480,1965 r270 top
J4 "691236510002" Wurth_691236510002 1980,2795 r180 top
J5 "691236510002" Wurth_691236510002 1580,2795 r180 top
J6 "691236510003" Wurth_691236510003 1480,2795 r180 top
J7 "HTSW-102-07-G-S" Samtec_HTSW-102-07-G-S 856.71,2956.69 r180 top
J8 "QTH-030-01-L-D-A" Samtec_QTH-030-01-x-D-A 1386,238 r180 top
J9 "HTSW-102-07-G-S" Samtec_HTSW-102-07-G-S 1280,2455.63 r0 top
J10 "HTSW-102-07-G-S" Samtec_HTSW-102-07-G-S 1769.3,2335.55 r270 top
J11 "HTSW-102-07-G-S" Samtec_HTSW-102-07-G-S 2315.89,2360.69 r270 top
J12 "HTSW-102-07-G-S" Samtec_HTSW-102-07-G-S 856.71,2804 r180 top
J13 "HTSW-102-07-G-S" Samtec_HTSW-102-07-G-S 839.64,2056.02 r0 top
J14 "HTSW-102-07-G-S" Samtec_HTSW-102-07-G-S 650.5,733.19 r0 top
J17 "HSEC8-160-01-L-DV-A-BL" controlCARD-120HSEC 322.13,1766.38 r270 top
J18 "687122149022" Wurth_687122149022 2744.74,238 r0 top
J19 "QSH-030-01-L-D-A" Samtec_QSH-030-01-X-D-A 2666,238 r90 top
K1 "TLP3420(TP,F" FP-TLP3420(TP,F_SMD4-MFG 3179.19,1994.65 r90 top
K2 "TLP3409S(TP,E" Omron_S-VSON4 3059.71,2078.42 r0 top
K3 "TLP3409S(TP,E" Omron_S-VSON4 2950.36,1908.48 r0 top
K4 "TLP3420(TP,F" FP-TLP3420(TP,F_SMD4-MFG 2816.44,1711.23 r270 top
K5 "TLP3420(TP,F" FP-TLP3420(TP,F_SMD4-MFG 2816.44,1809.06 r270 top
K6 "TLP3420(TP,F" FP-TLP3420(TP,F_SMD4-MFG 2816.44,1909.82 r270 top
K7 "TLP3420(TP,F" FP-TLP3420(TP,F_SMD4-MFG 2816.44,2003.86 r270 top
K8 "TLP3420(TP,F" FP-TLP3420(TP,F_SMD4-MFG 2816.44,2201.06 r270 top
K9 "TLP3420(TP,F" FP-TLP3420(TP,F_SMD4-MFG 2816.44,2094.17 r270 top
LBL1 "THT-14-423-10" Label_650x200 289.42,1527.97 r90 bottom
Logo1 "CE Mark" CE_Mark_5mm 285.68,816.02 r90 bottom
Logo2 "Texas Instruments" TI_Stacked_Overlay_Small 285.07,2298.65 r90 bottom
Logo3 "FCC disclaimer" FCC_disclaimer 68,1417.37 r90 bottom
Logo4 "WEEE logo" WEEE_Minimum 359.17,1082.99 r90 bottom
R1 "CRCW08052R00FKEA" 0805_HV 3108.52,1296.75 r180 bottom value=2.00
R2 "CRCW08052R00FKEA" 0805_HV 3108.52,1387.25 r180 bottom value=2.00
R3 "CRCW06033K01FKEA" 0603 2884.37,964.34 r0 top value=3.01k
R4 "CRCW080559K0FKEA" 0805_HV 3040.72,962.37 r180 top value=59.0k
R5 "CRCW080559K0FKEA" 0805_HV 3040.72,962.37 r180 bottom value=59.0k
R6 "CRCW080559K0FKEA" 0805_HV 2884.37,962.37 r0 bottom value=59.0k
R7 "CRCW06032K00FKEA" 0603 3390,1249.92 r270 bottom value=2.00k
R8 "CRCW06032K00FKEA" 0603 3205,962.37 r180 bottom value=2.00k
R9 "RK73H1ETTP1002F" 0402 3329,1153.38 r270 bottom value=10.0k
R10 "RK73H1ETTP1002F" 0402 3100.81,1585.97 r90 bottom value=10.0k
R11 "CRCW06032K00FKEA" 0603 3390,1424.46 r270 bottom value=2.00k
R12 "CRCW080559K0FKEA" 0805_HV 3390,1246.97 r270 top value=59.0k
R13 "CRCW080559K0FKEA" 0805_HV 3390,1088.52 r90 top value=59.0k
R14 "CRCW080559K0FKEA" 0805_HV 3390,1088.52 r90 bottom value=59.0k
R15 "CRCW080559K0FKEA" 0805_HV 3357.81,962.37 r180 top value=59.0k
R16 "CRCW080559K0FKEA" 0805_HV 3203.34,962.37 r0 top value=59.0k
R17 "CRCW080559K0FKEA" 0805_HV 3364.97,962.37 r180 bottom value=59.0k
R18 "CRCW08052R00FKEA" 0805_HV 2952.15,1296.75 r0 bottom value=2.00
R19 "CRCW08052R00FKEA" 0805_HV 2952.15,1387.25 r0 bottom value=2.00
R20 "RK73H1ETTP1002F" 0402 3027,1177 r270 bottom value=10.0k
R21 "RK73H1ETTP1002F" 0402 2779.54,1478.26 r90 bottom value=10.0k
R22 "CRCW04021K00FKED" 0402 3213.64,1892.74 r90 top value=1.00k
R23 "CRCW04021K00FKED" 0402 3021,2143 r0 top value=1.00k
R24 "ERJ-14BQF2R0U" 1210 3011.2,1755.51 r90 top value=2.00
R25 "CRCW0805100RFKEA" 0805_HV 3142.98,1868.48 r90 top value=100
R26 "CRCW0805100KFKEA" 0805_HV 3057.29,1950.18 r90 top value=100k
R27 "CRCW04020000Z0ED" 0402 3172.15,1687.99 r180 top value=0
R28 "CRCW04020000Z0ED" 0402 3151.98,1763.04 r180 top value=0
R29 "Y08502R00000F9R" FP-Y08502R00000F9R_2516-MFG 3096.71,1765.51 r180 bottom value=2
R30 "CRCW04021K00FKED" 0402 2945,1995 r270 top value=1.00k
R31 "CRCW04020000Z0ED" 0402 3350,1900 r270 top value=0
R32 "CRCW04020000Z0ED" 0402 2931,2163 r90 top value=0
R33 "CRCW04021K00FKED" 0402 2699.14,1726.97 r0 top value=1.00k
R34 "CRCW04021K00FKED" 0402 2699.14,1824.08 r0 top value=1.00k
R35 "CRCW04021K00FKED" 0402 2699.14,1924.23 r0 top value=1.00k
R36 "CRCW04021K00FKED" 0402 2699.14,2019.61 r0 top value=1.00k
R37 "CRCW04021K00FKED" 0402 2699.14,2109.92 r0 top value=1.00k
R38 "CRCW04021K00FKED" 0402 2699.14,2216.81 r0 top value=1.00k
R39 "CRCW0805200RFKEA" 0805_HV 3021,2143 r90 bottom value=200
R40 "RMCF0402JT100R" 0402 2846.35,2158.74 r270 bottom value=100
R41 "RMCF0402JT100R" 0402 2822.73,1696.64 r0 bottom value=100
R42 "ERJ-6ENF4532V" 0805_HV 3459,2240.6 r90 bottom value=45.3k
R43 "CRCW08055K00FKTA" FP-CRCW08055K00FKTA_0805-MFG 3450,2377.6 r90 bottom
R44 "CRCW0805200RFKEA" 0805_HV 3180,2295 r270 bottom value=200
R45 "RMCF0402JT100R" 0402 3350,1900 r270 bottom value=100
R46 "RMCF0402JT100R" 0402 2931,2163 r90 bottom value=100
R47 "CRCW04020000Z0ED" 0402 3021,2191 r180 top value=0
R48 "CRCW04020000Z0ED" 0402 1678.67,1340.29 r180 bottom value=0
R49 "CRCW04020000Z0ED" 0402 1680,1473.26 r0 bottom value=0
R50 "CRCW04020000Z0ED" 0402 1678.67,1384.22 r180 bottom value=0
R51 "CRCW04020000Z0ED" 0402 1805.14,1126.09 r0 bottom value=0
R52 "RMCF0402JT100R" 0402 1964.25,1717.41 r180 top value=100
R53 "RK73H1ETTP1002F" 0402 1775.71,1429.1 r0 top value=10.0k
R54 "CRCW04020000Z0ED" 0402 1775.71,1381.72 r180 top value=0
R55 "CRCW04020000Z0ED" 0402 1678.67,1428.76 r180 bottom value=0
R56 "RMCF0402JT100R" 0402 2013.46,1718.7 r0 bottom value=100
R57 "CRCW04021K00FKED" 0402 1775.71,1477.19 r180 top value=1.00k
R58 "RMCF0402JT100R" 0402 2013.46,1667.34 r0 bottom value=100
R59 "RMCF0402JT100R" 0402 1964.25,1672.14 r180 top value=100
R60 "CRCW04021K00FKED" 0402 1663.6,976.72 r180 bottom value=1.00k
R61 "CRCW04021K00FKED" 0402 1663.6,1026.72 r180 bottom value=1.00k
R62 "CRCW04020000Z0ED" 0402 1490.42,1334.57 r180 bottom value=0
R63 "CRCW04020000Z0ED" 0402 1514.04,1586.4 r0 bottom value=0
R64 "CRCW04021K00FKED" 0402 1579.44,1429.1 r180 bottom value=1.00k
R65 "RK73H1ETTP1002F" 0402 1579.44,1381.03 r0 bottom value=10.0k
R66 "CRCW04021K00FKED" 0402 1579.44,1477.19 r180 bottom value=1.00k
R67 "RK73H1ETTP1002F" 0402 1394.78,1151.5 r180 bottom value=10.0k
R68 "RK73H1ETTP1002F" 0402 1568.44,975.49 r180 bottom value=10.0k
R69 "RK73H1ETTP1002F" 0402 1394.78,1101.5 r180 bottom value=10.0k
R70 "RK73H1ETTP1002F" 0402 1568.44,930.01 r180 bottom value=10.0k
R71 "CRCW04020000Z0ED" 0402 1819.27,1236.21 r0 bottom value=0
R72 "CRCW080559K0FKEA" 0805_HV 3390,1575.25 r270 bottom value=59.0k
R73 "CRCW080559K0FKEA" 0805_HV 3390,1419.16 r90 top value=59.0k
R74 "CRCW080559K0FKEA" 0805_HV 3390,1575.25 r270 top value=59.0k
R75 "RK73H1ETTP1002F" 0402 1394.78,1055 r180 bottom value=10.0k
R76 "RK73H1ETTP1002F" 0402 1695,1230 r90 bottom value=10.0k
R77 "RK73H1ETTP1002F" 0402 1394.78,1015 r180 bottom value=10.0k
R78 "RK73H1ETTP1002F" 0402 1650,1230 r90 bottom value=10.0k
R79 "CRCW04020000Z0ED" 0402 1781.52,948.83 r0 bottom value=0
R80 "ERJ-6ENF2001V" 0805_HV 1956.48,1111.78 r0 bottom value=2.00k
R81 "CRCW04020000Z0ED" 0402 1781.52,993.67 r0 bottom value=0
R82 "ERJ-6ENF2001V" 0805_HV 1877.96,1166.09 r0 top value=2.00k
R83 "CRCW06032K00FKEA" 0603 2706.33,1249.92 r90 bottom value=2.00k
R84 "CRCW06032K00FKEA" 0603 2706.33,1424.46 r270 bottom value=2.00k
R85 "CRCW080559K0FKEA" 0805_HV 2704.42,1246.97 r270 top value=59.0k
R86 "CRCW040222K1FKED" 0402 1884.68,1038.36 r180 bottom value=22.1k
R87 "CRCW04020000Z0ED" 0402 1781.52,1038.95 r0 bottom value=0
R88 "CRCW04021K00FKED" 0402 1884.24,949.51 r180 bottom value=1.00k
R89 "CRCW04020000Z0ED" 0402 1751.82,1764.22 r180 bottom value=0
R90 "CRCW04021K00FKED" 0402 1884.24,993.67 r180 bottom value=1.00k
R91 "RMCF0402JT100R" 0402 1962.32,1518.07 r180 top value=100
R92 "RMCF0402JT100R" 0402 2014.05,1518.35 r0 bottom value=100
R93 "RMCF0402JT100R" 0402 2012.92,1565.74 r0 bottom value=100
R94 "CRCW04020000Z0ED" 0402 1721,1847 r270 bottom value=0
R95 "RMCF0402JT100R" 0402 1962.32,1567.68 r180 top value=100
R96 "CRCW080559K0FKEA" 0805_HV 2704.42,1088.52 r90 top value=59.0k
R97 "CRCW080559K0FKEA" 0805_HV 2704.42,1088.52 r90 bottom value=59.0k
R98 "CRCW080559K0FKEA" 0805_HV 2706.26,1575.25 r270 top value=59.0k
R99 "CRCW04020000Z0ED" 0402 1713,1848 r270 top value=0
R100 "RC0402FR-071ML" 0402 1377.4,834.83 r270 top value=1.00Meg
R101 "CRCW080559K0FKEA" 0805_HV 2704.42,1419.16 r90 top value=59.0k
R102 "CRCW080559K0FKEA" 0805_HV 2706.33,1575.25 r270 bottom value=59.0k
R103 "RMCF0402JT100R" 0402 1814.93,1457.51 r180 bottom value=100
R104 "CRCW04020000Z0ED" 0402 2014.01,939.2 r0 bottom value=0
R105 "RK73H1ETTP1002F" 0402 2014.01,983.45 r180 bottom value=10.0k
R106 "CRCW0402412RFKED" 0402 2064.51,834.18 r270 top value=412
R107 "RK73H1ETTP1002F" 0402 2064.51,834.18 r90 bottom value=10.0k
R108 "CRCW04024K99FKED" 0402 1776.42,839.31 r90 bottom value=4.99k
R109 "CRCW04022K00FKED" 0402 1776.09,741.28 r270 bottom value=2.00k
R110 "RC0402FR-071ML" 0402 2099.37,2880 r180 bottom value=1.00Meg
R111 "RMCF0402JT100R" 0402 2015.08,1032.71 r180 bottom value=100
R112 "CRCW04021K00FKED" 0402 2064.51,731.9 r90 bottom value=1.00k
R113 "RMCF0402JT100R" 0402 1859.6,2880 r180 bottom value=100
R114 "CRCW04020000Z0ED" 0402 2424.55,1391.51 r90 bottom value=0
R115 "RK73H1ETTP1002F" 0402 1047.21,1013.2 r90 bottom value=10.0k
R116 "RK73H1ETTP1002F" 0402 927.49,882.56 r180 bottom value=10.0k
R117 "RK73H1ETTP1002F" 0402 1097.41,1013.2 r270 bottom value=10.0k
R118 "RK73H1ETTP1002F" 0402 926.15,836.18 r180 bottom value=10.0k
R119 "CRCW04020000Z0ED" 0402 1149.8,892.29 r180 bottom value=0
R120 "RK73H1ETTP1002F" 0402 1646.42,762.47 r180 bottom value=10.0k
R121 "RMCF0402JT100R" 0402 1239.81,1620.51 r0 top value=100
R122 "CRCW040215K8FKED" 0402 1646.42,713.55 r180 bottom value=15.8k
R123 "RMCF0402JT100R" 0402 1528.31,839.46 r90 bottom value=100
R124 "RMCF0402JT100R" 0402 952.47,1381.03 r0 top value=100
R125 "RK73H1ETTP1002F" 0402 1020.85,1478.87 r270 bottom value=10.0k
R126 "RK73H1ETTP1002F" 0402 1094.62,1453.57 r0 bottom value=10.0k
R127 "RK73H1ETTP1002F" 0402 1094.62,1502.49 r180 bottom value=10.0k
R128 "CRCW04020000Z0ED" 0402 1239.81,1573.54 r180 bottom value=0
R129 "CRCW04020000Z0ED" 0402 1239.81,1573.54 r180 top value=0
R130 "RMCF0402JT100R" 0402 2076.36,1538.97 r90 bottom value=100
R131 "MCR01MZPF10R0" 0402 1703.1,495 r270 top value=10.0
R132 "CRCW040210R0FKED" 0402 1255.47,1796.35 r180 top value=10.0
R133 "MCR01MZPF10R0" 0402 1152.69,1844.19 r180 top value=10.0
R134 "CRCW04020000Z0ED" 0402 909.59,1905.74 r180 top value=0
R135 "RK73H1ETTP1002F" 0402 610,1835.3 r180 top value=10.0k
R136 "CRCW040210R0FKED" 0402 1255.47,1844.19 r180 top value=10.0
R137 "MCR01MZPF10R0" 0402 1152.69,1796.35 r180 top value=10.0
R138 "RMCF0402JT100R" 0402 1003.85,1790.44 r0 bottom value=100
R139 "MCR01MZPF10R0" 0402 1656.42,495 r270 top value=10.0
R140 "MCR01MZPF10R0" 0402 1749.79,495 r270 top value=10.0
R141 "CRCW04021K00FKED" 0402 960.07,1613.84 r270 top value=1.00k
R142 "CRCW04020000Z0ED" 0402 960.07,1613.84 r90 bottom value=0
R143 "CRCW040210R0FKED" 0402 1255.47,1702.73 r180 top value=10.0
R144 "MCR01MZPF10R0" 0402 1152.69,1748.55 r180 top value=10.0
R145 "CRCW040210R0FKED" 0402 1255.47,1748.55 r180 top value=10.0
R146 "MCR01MZPF10R0" 0402 1152.69,1702.73 r180 top value=10.0
R147 "RC0402FR-0782KL" 0402 1369.55,2090.23 r270 top value=82.0k
R148 "CRCW0402110KFKED" 0402 1218.06,2161.18 r180 top value=110k
R149 "RC0402FR-074K7L" 0402 1979.32,2092.32 r90 top value=4.70k
R150 "RK73H1ETTP1002F" 0402 1320.51,2090.23 r270 top value=10.0k
R151 "CRCW040252K3FKED" 0402 1931.06,2092.32 r270 top value=52.3k
R152 "RK73H1ETTP1002F" 0402 1218.45,2202.91 r180 top value=10.0k
R153 "RK73H1ETTP1002F" 0402 1931.06,2092.32 r270 bottom value=10.0k
R154 "CRCW040213K0FKED" 0402 1218.06,2116.69 r0 top value=13.0k
R155 "RC0402FR-071ML" 0402 2340.12,2042.03 r180 bottom value=1.00Meg
R156 "RC0402FR-07220KL" 0402 2340.12,2042.03 r0 top value=220k
R157 "RC0402FR-0782KL" 0402 768.5,2448.03 r180 top value=82.0k
R158 "CRCW0402110KFKED" 0402 738.5,2635 r90 top value=110k
R159 "RK73H1ETTP1002F" 0402 768.5,2493.86 r180 top value=10.0k
R160 "RK73H1ETTP1002F" 0402 791.4,2635 r90 top value=10.0k
R161 "CRCW040222K1FKED" 0402 2458.79,2042.03 r180 bottom value=22.1k
R162 "CRCW040213K0FKED" 0402 768.5,2541.89 r0 top value=13.0k
R163 "CRCW04021K00FKED" 0402 610,2389.56 r0 top value=1.00k
R164 "CRCW04022K20FKED" 0402 610,2341.65 r180 top value=2.20k
R165 "MCR01MZPF10R0" 0402 610,2298.37 r0 top value=10.0
R166 "MCR01MZPF10R0" 0402 610,2256.81 r0 top value=10.0
R167 "CRCW04021K00FKED" 0402 610.12,2214.24 r0 top value=1.00k
R168 "CRCW04022K20FKED" 0402 610,2169.39 r180 top value=2.20k
R169 "MCR01MZPF10R0" 0402 610,2066.73 r180 top value=10.0
R170 "MCR01MZPF10R0" 0402 610,1576 r0 top value=10.0
R171 "MCR01MZPF10R0" 0402 610,2026.43 r180 top value=10.0
R172 "MCR01MZPF10R0" 0402 610,1616.59 r0 top value=10.0
R173 "MCR01MZPF10R0" 0402 610,1981.07 r180 top value=10.0
R174 "MCR01MZPF10R0" 0402 610,1664.02 r0 top value=10.0
R175 "MCR01MZPF10R0" 0402 610,1933 r180 top value=10.0
R176 "CRCW04021K00FKED" 0402 610.12,955.99 r0 top value=1.00k
R177 "MCR01MZPF10R0" 0402 610,1880 r180 top value=10.0
R178 "MCR01MZPF10R0" 0402 610,1745.44 r180 top value=10.0
R179 "MCR01MZPF10R0" 0402 610,1705 r180 top value=10.0
R180 "MCR01MZPF10R0" 0402 610.12,1372.55 r180 top value=10.0
R181 "MCR01MZPF10R0" 0402 610,1533 r180 top value=10.0
R182 "MCR01MZPF10R0" 0402 610.12,1327.19 r180 top value=10.0
R183 "MCR01MZPF10R0" 0402 610,1789.25 r180 top value=10.0
R184 "MCR01MZPF10R0" 0402 610.12,1282.41 r180 top value=10.0
R185 "MCR01MZPF10R0" 0402 610,1142.28 r180 top value=10.0
R186 "MCR01MZPF10R0" 0402 610.12,1048.71 r180 top value=10.0
R187 "MCR01MZPF10R0" 0402 610.12,1190.34 r180 top value=10.0
R188 "MCR01MZPF10R0" 0402 610.12,1094.06 r180 top value=10.0
R189 "MCR01MZPF10R0" 0402 2835.14,530.72 r270 top value=10.0
R190 "MCR01MZPF10R0" 0402 2787.06,530.72 r270 top value=10.0
R191 "MCR01MZPF10R0" 0402 2737.93,530.72 r270 top value=10.0
R192 "MCR01MZPF10R0" 0402 2690.3,530.72 r270 top value=10.0
R193 "CRCW040210R0FKED" 0402 2699.14,652.34 r270 top value=10.0
R194 "CRCW040210R0FKED" 0402 2648.84,652.34 r270 top value=10.0
R195 "CRCW040210R0FKED" 0402 2601.72,652.34 r270 top value=10.0
R196 "CRCW040210R0FKED" 0402 2557.73,651.34 r270 top value=10.0
R197 "MCR01MZPF10R0" 0402 2606.76,155.65 r90 bottom value=10.0
R198 "CRCW040210R0FKED" 0402 2585.62,530.72 r270 top value=10.0
R199 "MCR01MZPF10R0" 0402 2563.11,155.65 r90 bottom value=10.0
R200 "CRCW040210R0FKED" 0402 2543.52,530.72 r270 top value=10.0
R201 "MCR01MZPF10R0" 0402 2520,155.65 r90 bottom value=10.0
R202 "CRCW040210R0FKED" 0402 2498.15,530.72 r270 top value=10.0
R203 "MCR01MZPF10R0" 0402 2475,155.65 r90 bottom value=10.0
R204 "RC0402FR-071ML" 0402 2526.72,555 r180 bottom value=1.00Meg
R205 "CRCW040210R0FKED" 0402 2453.46,530.72 r270 top value=10.0
R206 "MCR01MZPF10R0" 0402 2427.38,155.65 r90 bottom value=10.0
R207 "CRCW040210R0FKED" 0402 2410.59,530.72 r270 top value=10.0
R208 "RC0402FR-071ML" 0402 2427.38,555 r180 bottom value=1.00Meg
R209 "CRCW040210R0FKED" 0402 2366.34,530.72 r270 top value=10.0
R210 "RCWE0603R200FKEA" 0603 2890,2665 r180 bottom value=0.2
R211 "RCWE0603R200FKEA" 0603 2918.67,2505 r0 bottom value=0.2
R212 "RCWE0603R200FKEA" 0603 2670,2665 r0 bottom value=0.2
R213 "RCWE0603R200FKEA" 0603 2642,2505 r180 bottom value=0.2
R214 "MCR01MZPF10R0" 0402 1563.05,495 r270 top value=10.0
R215 "MCR01MZPF10R0" 0402 1516.37,495 r270 top value=10.0
R216 "MCR01MZPF10R0" 0402 1609.74,495 r270 top value=10.0
R217 "MCR01MZPF10R0" 0402 610,1487 r180 top value=10.0
R218 "MCR01MZPF10R0" 0402 1169.34,240 r270 bottom value=10.0
R219 "MCR01MZPF10R0" 0402 1122.4,240 r270 bottom value=10.0
R220 "MCR01MZPF10R0" 0402 1283,239 r90 bottom value=10.0
R221 "MCR01MZPF10R0" 0402 1218,240 r270 bottom value=10.0
R222 "MCR01MZPF10R0" 0402 1326.96,495 r270 top value=10.0
R223 "MCR01MZPF10R0" 0402 1279.64,495 r270 top value=10.0
R224 "MCR01MZPF10R0" 0402 1232.32,495 r270 top value=10.0
R225 "MCR01MZPF10R0" 0402 1185,495 r270 top value=10.0
R226 "MCR01MZPF10R0" 0402 1473,495 r270 top value=10.0
R227 "MCR01MZPF10R0" 0402 1432,495 r270 top value=10.0
R228 "CRCW04020000Z0ED" 0402 1387,495 r270 top value=0
R229 "RMCF0402JT100R" 0402 1880,1880 r270 bottom value=100
R230 "RK73H1ETTP1002F" 0402 1829,1918 r180 top value=10.0k
R231 "MCR01MZPF10R0" 0402 1554,263.62 r90 bottom value=10.0
R232 "CRCW04024K99FKED" 0402 1024.47,1286.58 r270 bottom value=4.99k
R233 "RMCF0402JT100R" 0402 1646.8,1887.22 r270 top value=100
R234 "RC0402FR-07220KL" 0402 1076,1286.58 r270 bottom value=220k
RN1 "Y0115V0030VV9L" FP-Y0115V0030VV9L_RADIAL-MFG 3373,2305.6 r270 top value=2/18kΩ
RN2 "PRES11A10QDDFRQ1" DDF0008A-MFG 1427.83,1477.19 r180 bottom
RN3 "PRES11A10QDDFRQ1" DDF0008A-MFG 1957.01,1233.37 r180 bottom
RN6 "PRES11A10QDDFRQ1" DDF0008A-MFG 1628.18,1847.53 r270 bottom
RN7 "PRES11A10QDDFRQ1" DDF0008A-MFG 1628.18,1666.23 r90 bottom
SH-J1 "60900213421" Wurth_60900213421 3993,66 r90 top
SH-J2 "60900213421" Wurth_60900213421 3710,3080 r180 top
SH-J3 "60900213421" Wurth_60900213421 3710,2815 r180 top
SH-J4 "60900213421" Wurth_60900213421 3643,66 r90 top
SH-J5 "60900213421" Wurth_60900213421 3710,2945 r180 top
SH-J6 "60900213421" Wurth_60900213421 3709,2673 r180 top
TP1 "5000" Keystone5000 3480,1785.5 r0 top
TP2 "5000" Keystone5000 3204.53,2476.5 r90 top
TP3 "5001" Keystone5001 3458.22,827.72 r90 top
TP5 "5001" Keystone5001 456.52,86 r90 top
TP6 "5001" Keystone5001 610,3025 r90 top
U1 "OPA593DNT" DNT0012B-MFG 3212.47,1137.62 r90 bottom
U2 "OPA593DNT" DNT0012B-MFG 3212.87,1541.17 r270 bottom
U3 "OPA593DNT" DNT0012B-MFG 2902.26,1137.62 r90 bottom
U4 "OPA593DNT" DNT0012B-MFG 2908.39,1541.17 r270 bottom
U5 "OPA454AIDDAR" DDA0008J 2817.05,1990 r0 bottom
U6 "OPA454AIDDAR" DDA0008J 3191,2064.7 r90 bottom
U7 "OPA596DBVR" DBV0005A-MFG 3000,2280 r180 top
U8 "OPA2182ID" D0008A-MFG 1541.88,1455.19 r0 top
U9 "PGA849RGTR" RGT0016J-MFG 1793.79,1641.52 r270 bottom
U10 "OPA2182ID" D0008A-MFG 1925.48,1013.36 r0 top
U11 "TMUX6221DGSR" DGS0010A-MFG 1960.2,1378.2 r180 bottom
U12 "TLV1872DGSR" DGS0010A-MFG 1585,1120 r0 bottom
U13 "OPA182IDBVR" DBV0005A-MFG 2002,1853 r0 bottom
U14 "OPA2182ID" D0008A-MFG 1585.25,1001.72 r0 top
U15 "PGA849RGTR" RGT0016J-MFG 1793.79,1641.52 r90 top
U16 "TMUX6219RQXR" RQX0008A-MFG 1836.79,1837.86 r180 top
U17 "TMUX6219RQXR" RQX0008A-MFG 1376.75,858.45 r270 bottom
U18 "TMUX6236RUMR" RUM0016E-MFG#1 1969.8,1379.19 r0 top
U19 "OPA2182ID" D0008A-MFG 1584.54,1229.02 r0 top
U20 "TMUX6219RQXR" RQX0008A-MFG 1995.2,1833.41 r270 top
U21 "TMUX6212RUMR" RUM0016E-MFG#2 1920.63,774.21 r180 bottom
U22 "TMUX6212RUMR" RUM0016E-MFG#2 1920.63,774.21 r270 top
U23 "TCAL9539RTW" RTW0024B-MFG 2331.28,1259.76 r270 top
U24 "TMUX6234RRQR" RRQ0020A-MFG 2336.19,1805.18 r180 top
U25 "TMUX6236RUMR" RUM0016E-MFG#1 2336.19,1529.81 r270 top
U26 "TCAL9539RTW" RTW0024B-MFG 2329.7,1013.55 r0 top
U27 "DAC11001BPFBT" PFB0048A-MFG 1067.88,885.4 r180 top
U28 "OPA4187IRUMR" RUM0016B-MFG 1296.35,1233.37 r0 top
U29 "REF54410CDR" D0008A-MFG 1007.06,1233.02 r180 top
U30 "OPA2182ID" D0008A-MFG 1587.37,787.89 r0 top
U31 "DAC80502DRX" DRX0010A 980.37,1477.19 r180 top
U32 "INA592IDRCR" DRC0010J-MFG 1237.92,1473.26 r180 bottom
U33 "INA592IDRCR" DRC0010J-MFG 1237.92,1473.26 r180 top
U34 "TPS7A2018PDQNR" DQN0004A-MFG 1027.76,1583.82 r270 top
U35 "OPA397DCKR" DCK0005A-MFG 1362.46,1843.57 r90 bottom
U36 "ADS9327VAE" VAE0022A-MFG 936.8,1783.64 r180 top
U37 "THS4552IRTWR" RTW0024A 1442.27,1755.97 r180 top
U38 "OPA397DCKR" DCK0005A-MFG 1360.57,1674.28 r90 bottom
U39 "TMUX6221DGSR" DGS0010A-MFG 2201.31,1586.44 r270 bottom
U40 "TPSM63603RDHR" RDH0030A-MFG 1438.25,2256.04 r90 top
U41 "TPSM82912RDUR" RDU0028A-MFG 1945.01,2284.59 r180 top
U42 "TPSM63603RDHR" RDH0030A-MFG 942.79,2382.8 r0 top
U43 "TPS7A9401DSC" DSC0010J-MFG 2354.31,2152.03 r0 top
U44 "OPA397DCKR" DCK0005A-MFG 1187.64,1296 r0 bottom

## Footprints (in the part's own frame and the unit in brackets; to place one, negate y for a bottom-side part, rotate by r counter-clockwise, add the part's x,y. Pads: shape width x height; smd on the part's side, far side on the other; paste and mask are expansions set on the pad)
0402 [mm] "0402 from SM-752 data"
  rect 0.8x0.6 smd: 1(-0.6,0) 2(0.6,0)
  silkscreen extent -1.22,-0.52 1.22,0.52, body extent -0.55,-0.3 0.55,0.3, height 0.6
0603 [mm] "0603 from SM-752 data"
  rect 1x0.95 smd: 1(-0.8,0) 2(0.8,0)
  silkscreen extent -1.52,-0.69 1.52,0.69, body extent -0.87,-0.47 0.87,0.47, height 1
0805_HV [mil] "0805 with 30mil clearance between pads"
  rect 50x63 smd: 1(-40,0) 2(40,0)
  silkscreen extent -74,-40 74,40, body extent -43,-29 43,29, height 57
1206 [mm] "1206 from SM-752 data"
  rect 1.3x1.85 smd: 1(-1.45,0) 2(1.45,0)
  silkscreen extent -2.4,-1.21 2.4,1.21, body extent -1.7,-0.9 1.7,0.9, height 1.35
1206_190 [mm] "1206_190"
  rect 1.1x1.6 smd: 1(-1.7,0) 2(1.7,0)
  silkscreen extent -0.9,-1 0.9,1, body extent -1.75,-0.95 1.75,0.95, height 1.9
1210 [mm] "1210 from SM-752 data"
  rect 1.3x2.7 smd: 1(-1.45,0) 2(1.45,0)
  silkscreen extent -2.32,-1.57 2.32,1.57, body extent -1.7,-1.35 1.7,1.35, height 1.35
CE_Mark_5mm [mil] "Minimum text height for CE Mark"
  silkscreen extent -138,-98 138,98
controlCARD-120HSEC [mm] "Pads are not numbered according to Samtec datasheet."
  rect 0.5x2.724 smd: 1(-23.357,-1.678) 2(-23.357,1.722) 3(-22.557,-1.678) 4(-22.557,1.722) 5(-21.757,-1.678) 6(-21.757,1.722) 7(-20.957,-1.678) 8(-20.957,1.722) 9(-20.157,-1.678) 10(-20.157,1.722) 11(-19.357,-1.678) 12(-19.357,1.722) 13(-18.557,-1.678) 14(-18.557,1.722) 15(-17.757,-1.678) 16(-17.757,1.722) 17(-16.957,-1.678) 18(-16.957,1.722) 19(-16.157,-1.678) 20(-16.157,1.722) 21(-15.357,-1.678) 22(-15.357,1.722) 23(-14.557,-1.678) 24(-14.557,1.722) 25(-13.757,-1.678) 26(-13.757,1.722) 27(-12.957,-1.678) 28(-12.957,1.722) 29(-12.157,-1.678) 30(-12.157,1.722) 31(-11.357,-1.678) 32(-11.357,1.722) 33(-10.557,-1.678) 34(-10.557,1.722) 35(-9.757,-1.678) 36(-9.757,1.722) 37(-8.957,-1.678) 38(-8.957,1.722) 39(-8.157,-1.678) 40(-8.157,1.722) 41(-7.357,-1.678) 42(-7.357,1.722) 43(-6.557,-1.678) 44(-6.557,1.722) 45(-5.757,-1.678) 46(-5.757,1.722) 47(-4.957,-1.678) 48(-4.957,1.722) 49(-4.157,-1.678) 50(-4.157,1.722) 51(-3.357,-1.678) 52(-3.357,1.722) 53(-2.557,-1.678) 54(-2.557,1.722) 55(-1.757,-1.678) 56(-1.757,1.722) 57(2.243,-1.678) 58(2.243,1.722) 59(3.043,-1.678) 60(3.043,1.722) 61(3.843,-1.678) 62(3.843,1.722) 63(4.643,-1.678) 64(4.643,1.722) 65(5.443,-1.678) 66(5.443,1.722) 67(6.243,-1.678) 68(6.243,1.722) 69(7.043,-1.678) 70(7.043,1.722) 71(7.843,-1.678) 72(7.843,1.722) 73(8.643,-1.678) 74(8.643,1.722) 75(9.443,-1.678) 76(9.443,1.722) 77(10.243,-1.678) 78(10.243,1.722) 79(11.043,-1.678) 80(11.043,1.722) 81(11.843,-1.678) 82(11.843,1.722) 83(12.643,-1.678) 84(12.643,1.722) 85(13.443,-1.678) 86(13.443,1.722) 87(14.243,-1.678) 88(14.243,1.722) 89(15.043,-1.678) 90(15.043,1.722) 91(15.843,-1.678) 92(15.843,1.722) 93(16.643,-1.678) 94(16.643,1.722) 95(17.443,-1.678) 96(17.443,1.722) 97(18.243,-1.678) 98(18.243,1.722) 99(19.043,-1.678) 100(19.043,1.722) 101(19.843,-1.678) 102(19.843,1.722) 103(20.643,-1.678) 104(20.643,1.722) 105(21.443,-1.678) 106(21.443,1.722) 107(22.243,-1.678) 108(22.243,1.722) 109(23.043,-1.678) 110(23.043,1.722) 111(23.843,-1.678) 112(23.843,1.722) 113(24.643,-1.678) 114(24.643,1.722) 115(25.443,-1.678) 116(25.443,1.722) 117(26.243,-1.678) 118(26.243,1.722) 119(27.043,-1.678) 120(27.043,1.722)
  round 0.025 hole 1.27 unplated mask+0.876: 181(-24.857,0.022) 182(28.543,1.522)
  round 1.348 hole 0.84: 185(-27.207,0.022) 186(30.893,0.022)
  silkscreen extent -32.11,-3.86 35.8,3.9, body extent -31.75,-3.48 35.3,3.52, height 12.35
D0008A-MFG [mm]
  rrect17% 1.55x0.6 smd paste+0 mask+0: 1(-2.7,1.905) 2(-2.7,0.635) 3(-2.7,-0.635) 4(-2.7,-1.905) 5(2.7,-1.905) 6(2.7,-0.635) 7(2.7,0.635) 8(2.7,1.905)
  silkscreen extent -4.17,-2.5 1.5,2.5, body extent -3.57,-2.75 3.57,2.75, height 0.25
DBV0005A-MFG [mm] "Recommended Land Pattern"
  rrect17% 1.1x0.6 smd paste+0 mask+0: 1(-1.3,0.95) 2(-1.3,0) 3(-1.3,-0.95) 4(1.3,-0.95) 5(1.3,0.95)
  silkscreen extent -2.58,-1.53 0.87,1.53, body extent -1.4,-1.45 1.4,1.45, height 1.45
DCK0005A-MFG [mm] "Recommended Land Pattern"
  rrect25% 0.95x0.4 smd paste+0 mask+0: 1(-1.1,0.65) 2(-1.1,0) 3(-1.1,-0.65) 4(1.1,-0.65) 5(1.1,0.65)
  silkscreen extent -2.25,-1.07 0.23,1.07, body extent -1.05,-1 1.05,1, height 1.1
DDA0008J [mm] "SOIC, 8-Leads, Body 4.9x3.9mm, Pitch 1.27mm, Exposed Pad"
  rrect14% 1.55x0.6 smd: 1(-2.7,1.905) 2(-2.7,0.635) 3(-2.7,-0.635) 4(-2.7,-1.905) 5(2.7,-1.905) 6(2.7,-0.635) 7(2.7,0.635) 8(2.7,1.905)
  rrect4% 2.95x4.9 smd paste-1.5 mask-1.5: 9(0,0)
  silkscreen extent -3.47,-2.55 1.58,2.55, body extent -3.01,-2.45 3.01,2.45, height 1.57
DDF0008A-MFG [mm]
  rrect22% 1.05x0.45 smd paste+0 mask+0: 1(-1.3,0.975) 2(-1.3,0.325) 3(-1.3,-0.325) 4(-1.3,-0.975) 5(1.3,-0.975) 6(1.3,-0.325) 7(1.3,0.325) 8(1.3,0.975)
  silkscreen extent -2.5,-1.48 0.4,1.48, body extent -1.41,-1.45 1.41,1.45, height 1.1
DGS0010A-MFG [mm] "Recommended Land Pattern"
  rrect33% 1.45x0.3 smd paste+0 mask+0: 1(-2.2,1) 2(-2.2,0.5) 3(-2.2,0) 4(-2.2,-0.5) 5(-2.2,-1) 6(2.2,-1) 7(2.2,-0.5) 8(2.2,0) 9(2.2,0.5) 10(2.2,1)
  silkscreen extent -3.6,-1.55 1.05,1.55, body extent -2.45,-1.5 2.45,1.5, height 1.1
